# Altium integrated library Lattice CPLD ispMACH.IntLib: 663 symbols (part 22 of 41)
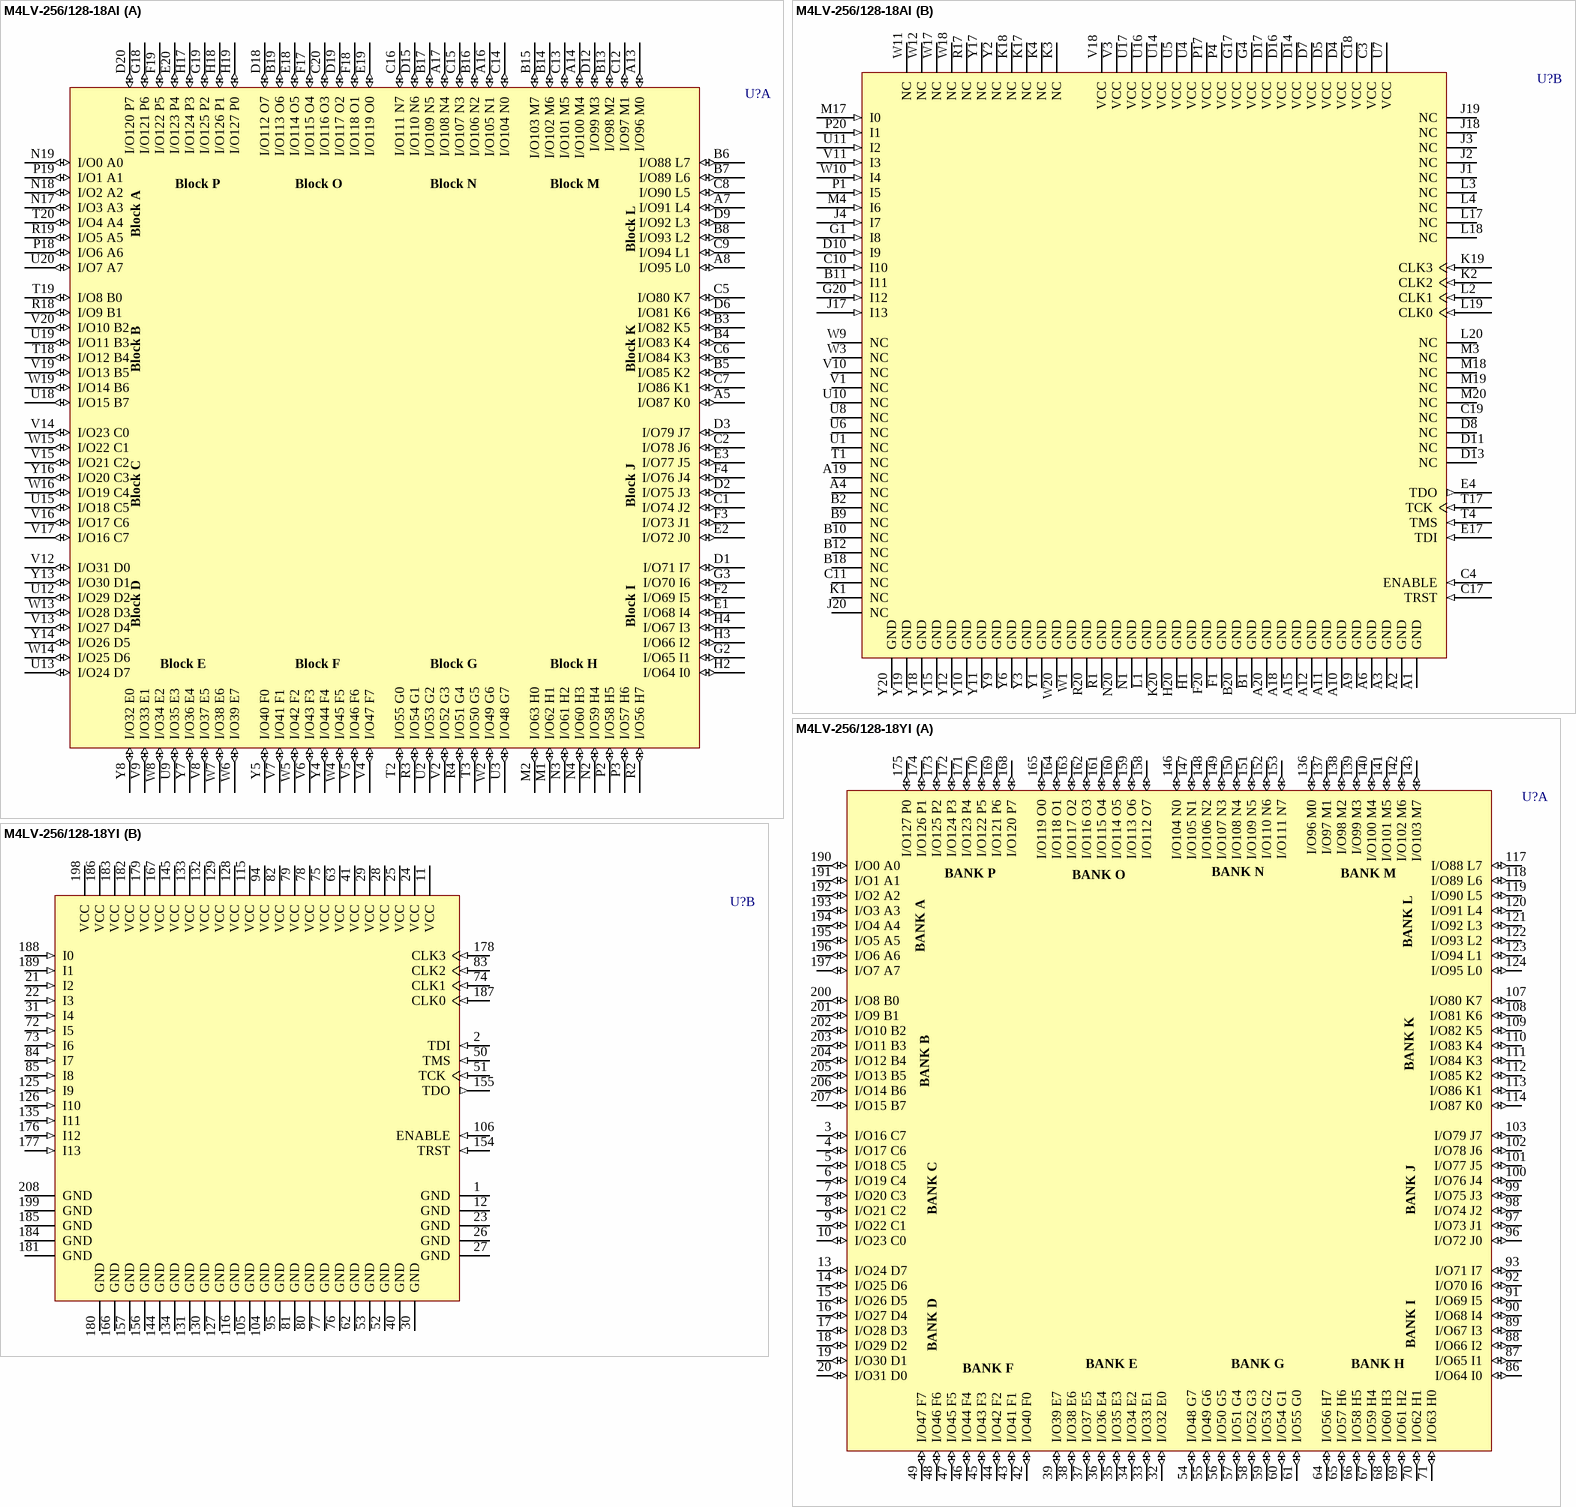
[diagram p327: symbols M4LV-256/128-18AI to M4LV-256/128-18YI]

## M4LV-256/128-18AI
designator U?
High-Performance EE CMOS In-System Programmable Logic
footprint SBGA256 (BGA, 256-Leads, Body 27x27mm, Pitch 1.27mm)
3D model M4LV-SBGA256 (256-Ball Super Ball Grid Array (SBGA256))
part A pins: A5 I/O87 K0 (io), A7 I/O91 L4 (io), A8 I/O95 L0 (io), A13 I/O96 M0 (io), A14 I/O100 M4 (io), A16 I/O105 N1 (io), A17 I/O108 N4 (io), B3 I/O82 K5 (io), B4 I/O83 K4 (io), B5 I/O85 K2 (io), B6 I/O88 L7 (io), B7 I/O89 L6 (io), B8 I/O93 L2 (io), B13 I/O98 M2 (io), B14 I/O102 M6 (io), B15 I/O103 M7 (io), B16 I/O106 N2 (io), B17 I/O109 N5 (io), B19 I/O113 O6 (io), C1 I/O74 J2 (io), C2 I/O78 J6 (io), C5 I/O80 K7 (io), C6 I/O84 K3 (io), C7 I/O86 K1 (io), C8 I/O90 L5 (io), C9 I/O94 L1 (io), C12 I/O97 M1 (io), C13 I/O101 M5 (io), C14 I/O104 N0 (io), C15 I/O107 N3 (io), C16 I/O111 N7 (io), C20 I/O116 O3 (io), D1 I/O71 I7 (io), D2 I/O75 J3 (io), D3 I/O79 J7 (io), D6 I/O81 K6 (io), D9 I/O92 L3 (io), D12 I/O99 M3 (io), D15 I/O110 N6 (io), D18 I/O112 O7 (io), D19 I/O117 O2 (io), D20 I/O120 P7 (io), E1 I/O68 I4 (io), E2 I/O72 J0 (io), E3 I/O77 J5 (io), E18 I/O114 O5 (io), E19 I/O119 O0 (io), E20 I/O123 P4 (io), F2 I/O69 I5 (io), F3 I/O73 J1 (io), F4 I/O76 J4 (io), F17 I/O115 O4 (io), F18 I/O118 O1 (io), F19 I/O122 P5 (io), G2 I/O65 I1 (io), G3 I/O70 I6 (io), G18 I/O121 P6 (io), G19 I/O125 P2 (io), H2 I/O64 I0 (io), H3 I/O66 I2 (io), H4 I/O67 I3 (io), H17 I/O124 P3 (io), H18 I/O126 P1 (io), H19 I/O127 P0 (io), M1 I/O62 H1 (io), M2 I/O63 H0 (io), N2 I/O59 H4 (io), N3 I/O61 H2 (io), N4 I/O60 H3 (io), N17 I/O3 A3 (io), N18 I/O2 A2 (io), N19 I/O0 A0 (io), P2 I/O58 H5 (io), P3 I/O57 H6 (io), P18 I/O6 A6 (io), P19 I/O1 A1 (io), R2 I/O56 H7 (io), R3 I/O54 G1 (io), R4 I/O51 G4 (io), R18 I/O9 B1 (io), R19 I/O5 A5 (io), T2 I/O55 G0 (io), T3 I/O50 G5 (io), T18 I/O12 B4 (io), T19 I/O8 B0 (io), T20 I/O4 A4 (io), U2 I/O53 G2 (io), U3 I/O48 G7 (io), U9 I/O35 E3 (io), U12 I/O29 D2 (io), U13 I/O24 D7 (io), U15 I/O18 C5 (io), U18 I/O15 B7 (io), U19 I/O11 B3 (io), U20 I/O7 A7 (io), V2 I/O52 G3 (io), V4 I/O47 F7 (io), V5 I/O46 F6 (io), V6 I/O43 F3 (io), V7 I/O41 F1 (io), V8 I/O37 E5 (io), V9 I/O33 E1 (io), V12 I/O31 D0 (io), V13 I/O27 D4 (io), V14 I/O23 C0 (io), V15 I/O21 C2 (io), V16 I/O17 C6 (io), V17 I/O16 C7 (io), V19 I/O13 B5 (io), V20 I/O10 B2 (io), W2 I/O49 G6 (io), W4 I/O45 F5 (io), W5 I/O42 F2 (io), W6 I/O39 E7 (io), W7 I/O38 E6 (io), W8 I/O34 E2 (io), W13 I/O28 D3 (io), W14 I/O25 D6 (io), W15 I/O22 C1 (io), W16 I/O19 C4 (io), W19 I/O14 B6 (io), Y4 I/O44 F4 (io), Y5 I/O40 F0 (io), Y7 I/O36 E4 (io), Y8 I/O32 E0 (io), Y13 I/O30 D1 (io), Y14 I/O26 D5 (io), Y16 I/O20 C3 (io)
part B pins: A1 GND (power), A2 GND (power), A3 GND (power), A4 NC, A6 GND (power), A9 GND (power), A10 GND (power), A11 GND (power), A12 GND (power), A15 GND (power), A18 GND (power), A19 NC, A20 GND (power), B1 GND (power), B2 NC, B9 NC, B10 NC, B11 I11 (in), B12 NC, B18 NC, B20 GND (power), C3 VCC (power), C4 ENABLE (in), C10 I10 (in), C11 NC, C17 TRST (in), C18 VCC (power), C19 NC, D4 VCC (power), D5 VCC (power), D7 VCC (power), D8 NC, D10 I9 (in), D11 NC, D13 NC, D14 VCC (power), D16 VCC (power), D17 VCC (power), E4 TDO (out), E17 TDI (in), F1 GND (power), F20 GND (power), G1 I8 (in), G4 VCC (power), G17 VCC (power), G20 I12 (in), H1 GND (power), H20 GND (power), J1 NC, J2 NC, J3 NC, J4 I7 (in), J17 I13 (in), J18 NC, J19 NC, J20 NC, K1 NC, K2 CLK2 (in), K3 NC, K4 NC, K17 NC, K18 NC, K19 CLK3 (in), K20 GND (power), L1 GND (power), L2 CLK1 (in), L3 NC, L4 NC, L17 NC, L18 NC, L19 CLK0 (in), L20 NC, M3 NC, M4 I6 (in), M17 I0 (in), M18 NC, M19 NC, M20 NC, N1 GND (power), N20 GND (power), P1 I5 (in), P4 VCC (power), P17 VCC (power), P20 I1 (in), R1 GND (power), R17 NC, R20 GND (power), T1 NC, T4 TMS (in), T17 TCK (in), U1 NC, U4 VCC (power), U5 VCC (power), U6 NC, U7 VCC (power), U8 NC, U10 NC, U11 I2 (in), U14 VCC (power), U16 VCC (power), U17 VCC (power), V1 NC, V3 VCC (power), V10 NC, V11 I3 (in), V18 VCC (power), W1 GND (power), W3 NC, W9 NC, W10 I4 (in), W11 NC, W12 NC, W17 NC, W18 NC, W20 GND (power), Y1 GND (power), Y2 NC, Y3 GND (power), Y6 GND (power), Y9 GND (power), Y10 GND (power), Y11 GND (power), Y12 GND (power), Y15 GND (power), Y17 NC, Y18 GND (power), Y19 GND (power), Y20 GND (power)

## M4LV-256/128-18YI
designator U?
High-Performance EE CMOS In-System Programmable Logic
footprint PQFP208_N (Shrink QFP, 208-Leads, Body 28x28mm, Pitch 0.5mm, IPC Medium Density)
footprint PQFP208_L (Shrink QFP, 208-Leads, Body 28x28mm, Pitch 0.5mm, IPC High Density)
footprint PQFP208_M (Shrink QFP, 208-Leads, Body 28x28mm, Pitch 0.5mm, IPC Low Density)
3D model M4LV-PQFP208 (208-Pin Plastic Quad Flat Pack (PQFP208))
part A pins: 3 I/O16 C7 (io), 4 I/O17 C6 (io), 5 I/O18 C5 (io), 6 I/O19 C4 (io), 7 I/O20 C3 (io), 8 I/O21 C2 (io), 9 I/O22 C1 (io), 10 I/O23 C0 (io), 13 I/O24 D7 (io), 14 I/O25 D6 (io), 15 I/O26 D5 (io), 16 I/O27 D4 (io), 17 I/O28 D3 (io), 18 I/O29 D2 (io), 19 I/O30 D1 (io), 20 I/O31 D0 (io), 32 I/O32 E0 (io), 33 I/O33 E1 (io), 34 I/O34 E2 (io), 35 I/O35 E3 (io), 36 I/O36 E4 (io), 37 I/O37 E5 (io), 38 I/O38 E6 (io), 39 I/O39 E7 (io), 42 I/O40 F0 (io), 43 I/O41 F1 (io), 44 I/O42 F2 (io), 45 I/O43 F3 (io), 46 I/O44 F4 (io), 47 I/O45 F5 (io), 48 I/O46 F6 (io), 49 I/O47 F7 (io), 54 I/O48 G7 (io), 55 I/O49 G6 (io), 56 I/O50 G5 (io), 57 I/O51 G4 (io), 58 I/O52 G3 (io), 59 I/O53 G2 (io), 60 I/O54 G1 (io), 61 I/O55 G0 (io), 64 I/O56 H7 (io), 65 I/O57 H6 (io), 66 I/O58 H5 (io), 67 I/O59 H4 (io), 68 I/O60 H3 (io), 69 I/O61 H2 (io), 70 I/O62 H1 (io), 71 I/O63 H0 (io), 86 I/O64 I0 (io), 87 I/O65 I1 (io), 88 I/O66 I2 (io), 89 I/O67 I3 (io), 90 I/O68 I4 (io), 91 I/O69 I5 (io), 92 I/O70 I6 (io), 93 I/O71 I7 (io), 96 I/O72 J0 (io), 97 I/O73 J1 (io), 98 I/O74 J2 (io), 99 I/O75 J3 (io), 100 I/O76 J4 (io), 101 I/O77 J5 (io), 102 I/O78 J6 (io), 103 I/O79 J7 (io), 107 I/O80 K7 (io), 108 I/O81 K6 (io), 109 I/O82 K5 (io), 110 I/O83 K4 (io), 111 I/O84 K3 (io), 112 I/O85 K2 (io), 113 I/O86 K1 (io), 114 I/O87 K0 (io), 117 I/O88 L7 (io), 118 I/O89 L6 (io), 119 I/O90 L5 (io), 120 I/O91 L4 (io), 121 I/O92 L3 (io), 122 I/O93 L2 (io), 123 I/O94 L1 (io), 124 I/O95 L0 (io), 136 I/O96 M0 (io), 137 I/O97 M1 (io), 138 I/O98 M2 (io), 139 I/O99 M3 (io), 140 I/O100 M4 (io), 141 I/O101 M5 (io), 142 I/O102 M6 (io), 143 I/O103 M7 (io), 146 I/O104 N0 (io), 147 I/O105 N1 (io), 148 I/O106 N2 (io), 149 I/O107 N3 (io), 150 I/O108 N4 (io), 151 I/O109 N5 (io), 152 I/O110 N6 (io), 153 I/O111 N7 (io), 158 I/O112 O7 (io), 159 I/O113 O6 (io), 160 I/O114 O5 (io), 161 I/O115 O4 (io), 162 I/O116 O3 (io), 163 I/O117 O2 (io), 164 I/O118 O1 (io), 165 I/O119 O0 (io), 168 I/O120 P7 (io), 169 I/O121 P6 (io), 170 I/O122 P5 (io), 171 I/O123 P4 (io), 172 I/O124 P3 (io), 173 I/O125 P2 (io), 174 I/O126 P1 (io), 175 I/O127 P0 (io), 190 I/O0 A0 (io), 191 I/O1 A1 (io), 192 I/O2 A2 (io), 193 I/O3 A3 (io), 194 I/O4 A4 (io), 195 I/O5 A5 (io), 196 I/O6 A6 (io), 197 I/O7 A7 (io), 200 I/O8 B0 (io), 201 I/O9 B1 (io), 202 I/O10 B2 (io), 203 I/O11 B3 (io), 204 I/O12 B4 (io), 205 I/O13 B5 (io), 206 I/O14 B6 (io), 207 I/O15 B7 (io)
part B pins: 1 GND (power), 2 TDI (in), 11 VCC (power), 12 GND (power), 21 I2 (in), 22 I3 (in), 23 GND (power), 24 VCC (power), 25 VCC (power), 26 GND (power), 27 GND (power), 28 VCC (power), 29 VCC (power), 30 GND (power), 31 I4 (in), 40 GND (power), 41 VCC (power), 50 TMS (in), 51 TCK (in), 52 GND (power), 53 GND (power), 62 GND (power), 63 VCC (power), 72 I5 (in), 73 I6 (in), 74 CLK1 (in), 75 VCC (power), 76 GND (power), 77 GND (power), 78 VCC (power), 79 VCC (power), 80 GND (power), 81 GND (power), 82 VCC (power), 83 CLK2 (in), 84 I7 (in), 85 I8 (in), 94 VCC (power), 95 GND (power), 104 GND (power), 105 GND (power), 106 ENABLE (in), 115 VCC (power), 116 GND (power), 125 I9 (in), 126 I10 (in), 127 GND (power), 128 VCC (power), 129 VCC (power), 130 GND (power), 131 GND (power), 132 VCC (power), 133 VCC (power), 134 GND (power), 135 I11 (in), 144 GND (power), 145 VCC (power), 154 TRST (in), 155 TDO (out), 156 GND (power), 157 GND (power), 166 GND (power), 167 VCC (power), 176 I12 (in), 177 I13 (in), 178 CLK3 (in), 179 VCC (power), 180 GND (power), 181 GND (power), 182 VCC (power), 183 VCC (power), 184 GND (power), 185 GND (power), 186 VCC (power), 187 CLK0 (in), 188 I0 (in), 189 I1 (in), 198 VCC (power), 199 GND (power), 208 GND (power)

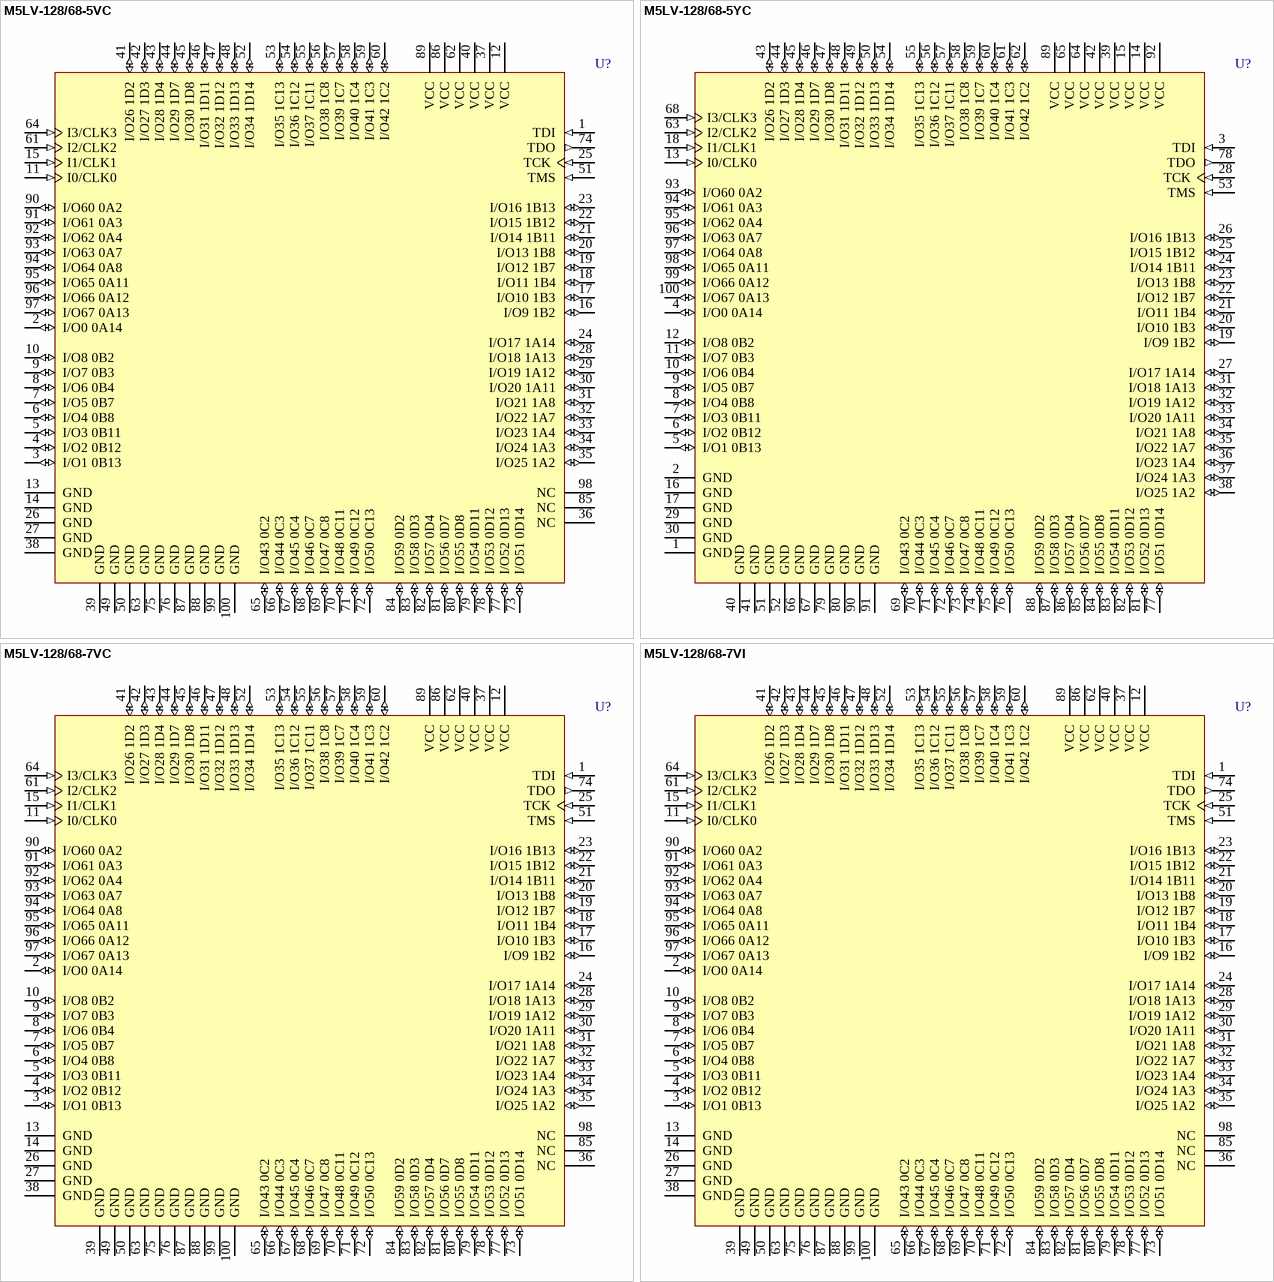
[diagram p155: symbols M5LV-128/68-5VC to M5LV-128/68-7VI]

## M5LV-128/68-5VC
designator U?
High-Density and High-I/O Complex PLD
footprint TQFP100_N (Thin QFP, 100-Leads, Body 14x14mm, Pitch 0.5mm, IPC Medium Density)
footprint TQFP100_L (Thin QFP, 100-Leads, Body 14x14mm, Pitch 0.5mm, IPC High Density)
footprint TQFP100_M (Thin QFP, 100-Leads, Body 14x14mm, Pitch 0.5mm, IPC Low Density)
3D model M5LV-TQFP100 (100-Pin Thin Quad Flat Pack (TQFP100))
pins: 1 TDI (in), 2 I/O0 0A14 (io), 3 I/O1 0B13 (io), 4 I/O2 0B12 (io), 5 I/O3 0B11 (io), 6 I/O4 0B8 (io), 7 I/O5 0B7 (io), 8 I/O6 0B4 (io), 9 I/O7 0B3 (io), 10 I/O8 0B2 (io), 11 I0/CLK0 (in), 12 VCC (power), 13 GND (power), 14 GND (power), 15 I1/CLK1 (in), 16 I/O9 1B2 (io), 17 I/O10 1B3 (io), 18 I/O11 1B4 (io), 19 I/O12 1B7 (io), 20 I/O13 1B8 (io), 21 I/O14 1B11 (io), 22 I/O15 1B12 (io), 23 I/O16 1B13 (io), 24 I/O17 1A14 (io), 25 TCK (in), 26 GND (power), 27 GND (power), 28 I/O18 1A13 (io), 29 I/O19 1A12 (io), 30 I/O20 1A11 (io), 31 I/O21 1A8 (io), 32 I/O22 1A7 (io), 33 I/O23 1A4 (io), 34 I/O24 1A3 (io), 35 I/O25 1A2 (io), 36 NC, 37 VCC (power), 38 GND (power), 39 GND (power), 40 VCC (power), 41 I/O26 1D2 (io), 42 I/O27 1D3 (io), 43 I/O28 1D4 (io), 44 I/O29 1D7 (io), 45 I/O30 1D8 (io), 46 I/O31 1D11 (io), 47 I/O32 1D12 (io), 48 I/O33 1D13 (io), 49 GND (power), 50 GND (power), 51 TMS (in), 52 I/O34 1D14 (io), 53 I/O35 1C13 (io), 54 I/O36 1C12 (io), 55 I/O37 1C11 (io), 56 I/O38 1C8 (io), 57 I/O39 1C7 (io), 58 I/O40 1C4 (io), 59 I/O41 1C3 (io), 60 I/O42 1C2 (io), 61 I2/CLK2 (in), 62 VCC (power), 63 GND (power), 64 I3/CLK3 (in), 65 I/O43 0C2 (io), 66 I/O44 0C3 (io), 67 I/O45 0C4 (io), 68 I/O46 0C7 (io), 69 I/O47 0C8 (io), 70 I/O48 0C11 (io), 71 I/O49 0C12 (io), 72 I/O50 0C13 (io), 73 I/O51 0D14 (io), 74 TDO (out), 75 GND (power), 76 GND (power), 77 I/O52 0D13 (io), 78 I/O53 0D12 (io), 79 I/O54 0D11 (io), 80 I/O55 0D8 (io), 81 I/O56 0D7 (io), 82 I/O57 0D4 (io), 83 I/O58 0D3 (io), 84 I/O59 0D2 (io), 85 NC, 86 VCC (power), 87 GND (power), 88 GND (power), 89 VCC (power), 90 I/O60 0A2 (io), 91 I/O61 0A3 (io), 92 I/O62 0A4 (io), 93 I/O63 0A7 (io), 94 I/O64 0A8 (io), 95 I/O65 0A11 (io), 96 I/O66 0A12 (io), 97 I/O67 0A13 (io), 98 NC, 99 GND (power), 100 GND (power)

## M5LV-128/68-5YC
designator U?
High-Density and High-I/O Complex PLD
footprint PQFP100_N (QFP, 100-Leads, Body 20x14mm, Pitch 0.65mm, IPC Medium Density)
footprint PQFP100_L (QFP, 100-Leads, Body 20x14mm, Pitch 0.65mm, IPC High Density)
footprint PQFP100_M (QFP, 100-Leads, Body 20x14mm, Pitch 0.65mm, IPC Low Density)
3D model PQFP-100 (100-Pin Quad Flat Pack Rectangular 0.65 mm Pitch)
pins: 1 GND (power), 2 GND (power), 3 TDI (in), 4 I/O0 0A14 (io), 5 I/O1 0B13 (io), 6 I/O2 0B12 (io), 7 I/O3 0B11 (io), 8 I/O4 0B8 (io), 9 I/O5 0B7 (io), 10 I/O6 0B4 (io), 11 I/O7 0B3 (io), 12 I/O8 0B2 (io), 13 I0/CLK0 (in), 14 VCC (power), 15 VCC (power), 16 GND (power), 17 GND (power), 18 I1/CLK1 (in), 19 I/O9 1B2 (io), 20 I/O10 1B3 (io), 21 I/O11 1B4 (io), 22 I/O12 1B7 (io), 23 I/O13 1B8 (io), 24 I/O14 1B11 (io), 25 I/O15 1B12 (io), 26 I/O16 1B13 (io), 27 I/O17 1A14 (io), 28 TCK (in), 29 GND (power), 30 GND (power), 31 I/O18 1A13 (io), 32 I/O19 1A12 (io), 33 I/O20 1A11 (io), 34 I/O21 1A8 (io), 35 I/O22 1A7 (io), 36 I/O23 1A4 (io), 37 I/O24 1A3 (io), 38 I/O25 1A2 (io), 39 VCC (power), 40 GND (power), 41 GND (power), 42 VCC (power), 43 I/O26 1D2 (io), 44 I/O27 1D3 (io), 45 I/O28 1D4 (io), 46 I/O29 1D7 (io), 47 I/O30 1D8 (io), 48 I/O31 1D11 (io), 49 I/O32 1D12 (io), 50 I/O33 1D13 (io), 51 GND (power), 52 GND (power), 53 TMS (in), 54 I/O34 1D14 (io), 55 I/O35 1C13 (io), 56 I/O36 1C12 (io), 57 I/O37 1C11 (io), 58 I/O38 1C8 (io), 59 I/O39 1C7 (io), 60 I/O40 1C4 (io), 61 I/O41 1C3 (io), 62 I/O42 1C2 (io), 63 I2/CLK2 (in), 64 VCC (power), 65 VCC (power), 66 GND (power), 67 GND (power), 68 I3/CLK3 (in), 69 I/O43 0C2 (io), 70 I/O44 0C3 (io), 71 I/O45 0C4 (io), 72 I/O46 0C7 (io), 73 I/O47 0C8 (io), 74 I/O48 0C11 (io), 75 I/O49 0C12 (io), 76 I/O50 0C13 (io), 77 I/O51 0D14 (io), 78 TDO (out), 79 GND (power), 80 GND (power), 81 I/O52 0D13 (io), 82 I/O53 0D12 (io), 83 I/O54 0D11 (io), 84 I/O55 0D8 (io), 85 I/O56 0D7 (io), 86 I/O57 0D4 (io), 87 I/O58 0D3 (io), 88 I/O59 0D2 (io), 89 VCC (power), 90 GND (power), 91 GND (power), 92 VCC (power), 93 I/O60 0A2 (io), 94 I/O61 0A3 (io), 95 I/O62 0A4 (io), 96 I/O63 0A7 (io), 97 I/O64 0A8 (io), 98 I/O65 0A11 (io), 99 I/O66 0A12 (io), 100 I/O67 0A13 (io)

## M5LV-128/68-7VC
designator U?
High-Density and High-I/O Complex PLD
footprint TQFP100_N (Thin QFP, 100-Leads, Body 14x14mm, Pitch 0.5mm, IPC Medium Density)
footprint TQFP100_L (Thin QFP, 100-Leads, Body 14x14mm, Pitch 0.5mm, IPC High Density)
footprint TQFP100_M (Thin QFP, 100-Leads, Body 14x14mm, Pitch 0.5mm, IPC Low Density)
3D model M5LV-TQFP100 (100-Pin Thin Quad Flat Pack (TQFP100))
pins: 1 TDI (in), 2 I/O0 0A14 (io), 3 I/O1 0B13 (io), 4 I/O2 0B12 (io), 5 I/O3 0B11 (io), 6 I/O4 0B8 (io), 7 I/O5 0B7 (io), 8 I/O6 0B4 (io), 9 I/O7 0B3 (io), 10 I/O8 0B2 (io), 11 I0/CLK0 (in), 12 VCC (power), 13 GND (power), 14 GND (power), 15 I1/CLK1 (in), 16 I/O9 1B2 (io), 17 I/O10 1B3 (io), 18 I/O11 1B4 (io), 19 I/O12 1B7 (io), 20 I/O13 1B8 (io), 21 I/O14 1B11 (io), 22 I/O15 1B12 (io), 23 I/O16 1B13 (io), 24 I/O17 1A14 (io), 25 TCK (in), 26 GND (power), 27 GND (power), 28 I/O18 1A13 (io), 29 I/O19 1A12 (io), 30 I/O20 1A11 (io), 31 I/O21 1A8 (io), 32 I/O22 1A7 (io), 33 I/O23 1A4 (io), 34 I/O24 1A3 (io), 35 I/O25 1A2 (io), 36 NC, 37 VCC (power), 38 GND (power), 39 GND (power), 40 VCC (power), 41 I/O26 1D2 (io), 42 I/O27 1D3 (io), 43 I/O28 1D4 (io), 44 I/O29 1D7 (io), 45 I/O30 1D8 (io), 46 I/O31 1D11 (io), 47 I/O32 1D12 (io), 48 I/O33 1D13 (io), 49 GND (power), 50 GND (power), 51 TMS (in), 52 I/O34 1D14 (io), 53 I/O35 1C13 (io), 54 I/O36 1C12 (io), 55 I/O37 1C11 (io), 56 I/O38 1C8 (io), 57 I/O39 1C7 (io), 58 I/O40 1C4 (io), 59 I/O41 1C3 (io), 60 I/O42 1C2 (io), 61 I2/CLK2 (in), 62 VCC (power), 63 GND (power), 64 I3/CLK3 (in), 65 I/O43 0C2 (io), 66 I/O44 0C3 (io), 67 I/O45 0C4 (io), 68 I/O46 0C7 (io), 69 I/O47 0C8 (io), 70 I/O48 0C11 (io), 71 I/O49 0C12 (io), 72 I/O50 0C13 (io), 73 I/O51 0D14 (io), 74 TDO (out), 75 GND (power), 76 GND (power), 77 I/O52 0D13 (io), 78 I/O53 0D12 (io), 79 I/O54 0D11 (io), 80 I/O55 0D8 (io), 81 I/O56 0D7 (io), 82 I/O57 0D4 (io), 83 I/O58 0D3 (io), 84 I/O59 0D2 (io), 85 NC, 86 VCC (power), 87 GND (power), 88 GND (power), 89 VCC (power), 90 I/O60 0A2 (io), 91 I/O61 0A3 (io), 92 I/O62 0A4 (io), 93 I/O63 0A7 (io), 94 I/O64 0A8 (io), 95 I/O65 0A11 (io), 96 I/O66 0A12 (io), 97 I/O67 0A13 (io), 98 NC, 99 GND (power), 100 GND (power)

## M5LV-128/68-7VI
designator U?
High-Density and High-I/O Complex PLD
footprint TQFP100_N (Thin QFP, 100-Leads, Body 14x14mm, Pitch 0.5mm, IPC Medium Density)
footprint TQFP100_L (Thin QFP, 100-Leads, Body 14x14mm, Pitch 0.5mm, IPC High Density)
footprint TQFP100_M (Thin QFP, 100-Leads, Body 14x14mm, Pitch 0.5mm, IPC Low Density)
3D model M5LV-TQFP100 (100-Pin Thin Quad Flat Pack (TQFP100))
pins: 1 TDI (in), 2 I/O0 0A14 (io), 3 I/O1 0B13 (io), 4 I/O2 0B12 (io), 5 I/O3 0B11 (io), 6 I/O4 0B8 (io), 7 I/O5 0B7 (io), 8 I/O6 0B4 (io), 9 I/O7 0B3 (io), 10 I/O8 0B2 (io), 11 I0/CLK0 (in), 12 VCC (power), 13 GND (power), 14 GND (power), 15 I1/CLK1 (in), 16 I/O9 1B2 (io), 17 I/O10 1B3 (io), 18 I/O11 1B4 (io), 19 I/O12 1B7 (io), 20 I/O13 1B8 (io), 21 I/O14 1B11 (io), 22 I/O15 1B12 (io), 23 I/O16 1B13 (io), 24 I/O17 1A14 (io), 25 TCK (in), 26 GND (power), 27 GND (power), 28 I/O18 1A13 (io), 29 I/O19 1A12 (io), 30 I/O20 1A11 (io), 31 I/O21 1A8 (io), 32 I/O22 1A7 (io), 33 I/O23 1A4 (io), 34 I/O24 1A3 (io), 35 I/O25 1A2 (io), 36 NC, 37 VCC (power), 38 GND (power), 39 GND (power), 40 VCC (power), 41 I/O26 1D2 (io), 42 I/O27 1D3 (io), 43 I/O28 1D4 (io), 44 I/O29 1D7 (io), 45 I/O30 1D8 (io), 46 I/O31 1D11 (io), 47 I/O32 1D12 (io), 48 I/O33 1D13 (io), 49 GND (power), 50 GND (power), 51 TMS (in), 52 I/O34 1D14 (io), 53 I/O35 1C13 (io), 54 I/O36 1C12 (io), 55 I/O37 1C11 (io), 56 I/O38 1C8 (io), 57 I/O39 1C7 (io), 58 I/O40 1C4 (io), 59 I/O41 1C3 (io), 60 I/O42 1C2 (io), 61 I2/CLK2 (in), 62 VCC (power), 63 GND (power), 64 I3/CLK3 (in), 65 I/O43 0C2 (io), 66 I/O44 0C3 (io), 67 I/O45 0C4 (io), 68 I/O46 0C7 (io), 69 I/O47 0C8 (io), 70 I/O48 0C11 (io), 71 I/O49 0C12 (io), 72 I/O50 0C13 (io), 73 I/O51 0D14 (io), 74 TDO (out), 75 GND (power), 76 GND (power), 77 I/O52 0D13 (io), 78 I/O53 0D12 (io), 79 I/O54 0D11 (io), 80 I/O55 0D8 (io), 81 I/O56 0D7 (io), 82 I/O57 0D4 (io), 83 I/O58 0D3 (io), 84 I/O59 0D2 (io), 85 NC, 86 VCC (power), 87 GND (power), 88 GND (power), 89 VCC (power), 90 I/O60 0A2 (io), 91 I/O61 0A3 (io), 92 I/O62 0A4 (io), 93 I/O63 0A7 (io), 94 I/O64 0A8 (io), 95 I/O65 0A11 (io), 96 I/O66 0A12 (io), 97 I/O67 0A13 (io), 98 NC, 99 GND (power), 100 GND (power)

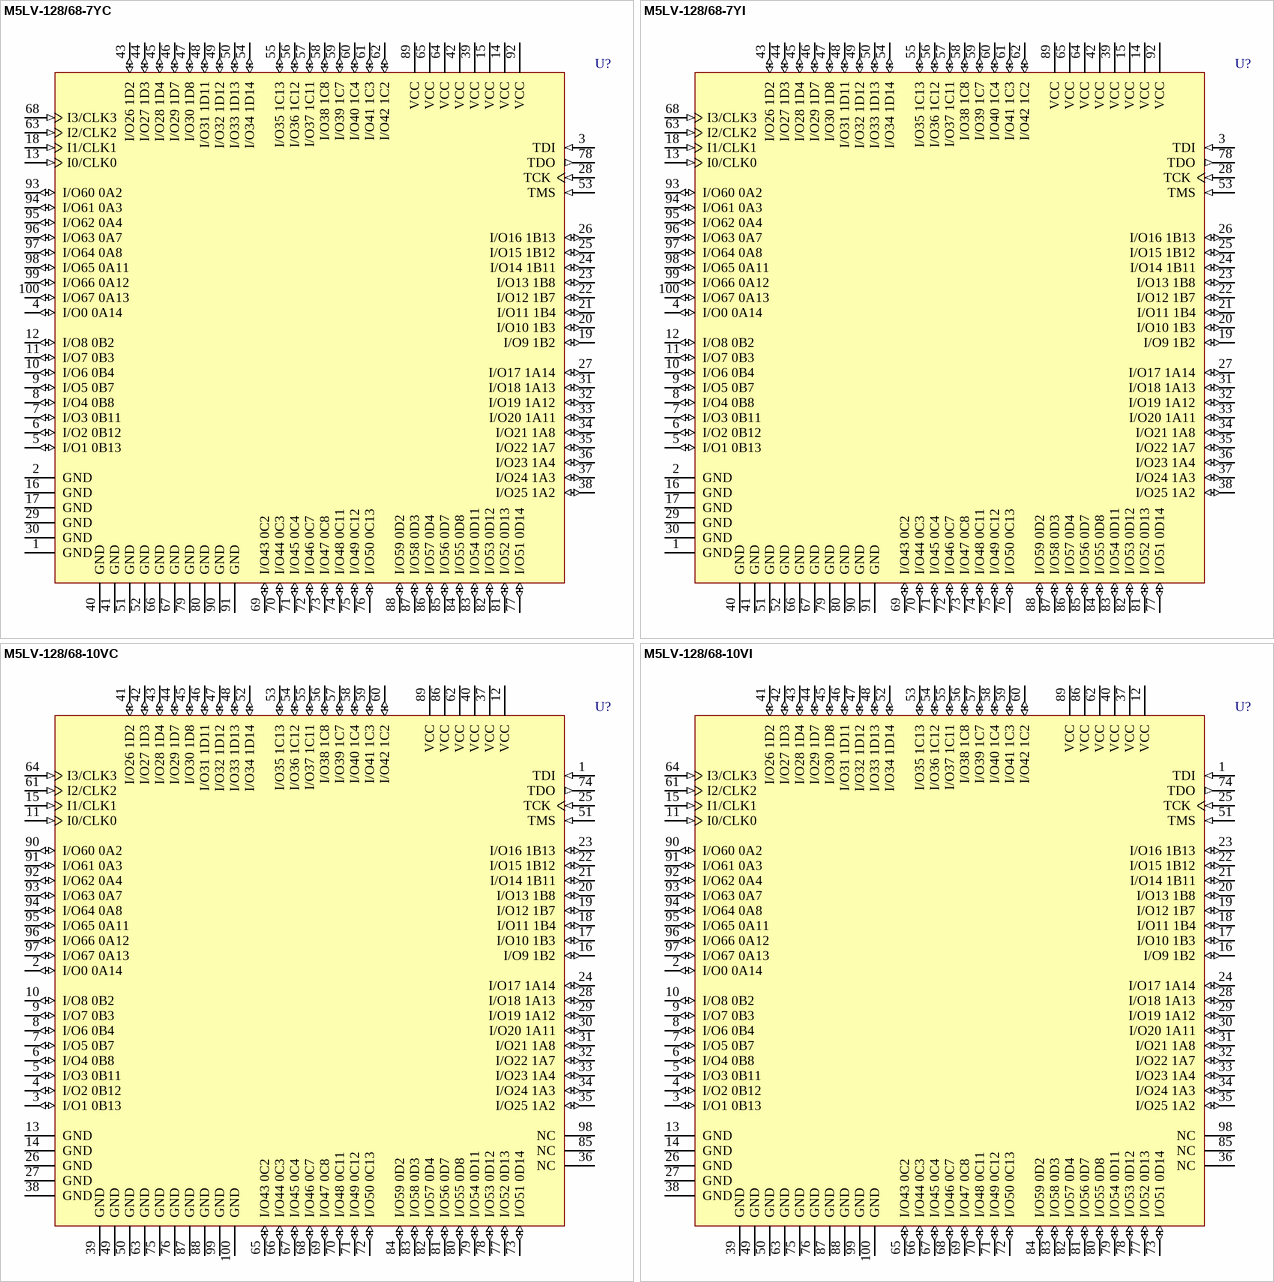
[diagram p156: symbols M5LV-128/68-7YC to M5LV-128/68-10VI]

## M5LV-128/68-7YC
designator U?
High-Density and High-I/O Complex PLD
footprint PQFP100_N (QFP, 100-Leads, Body 20x14mm, Pitch 0.65mm, IPC Medium Density)
footprint PQFP100_L (QFP, 100-Leads, Body 20x14mm, Pitch 0.65mm, IPC High Density)
footprint PQFP100_M (QFP, 100-Leads, Body 20x14mm, Pitch 0.65mm, IPC Low Density)
3D model PQFP-100 (100-Pin Quad Flat Pack Rectangular 0.65 mm Pitch)
pins: 1 GND (power), 2 GND (power), 3 TDI (in), 4 I/O0 0A14 (io), 5 I/O1 0B13 (io), 6 I/O2 0B12 (io), 7 I/O3 0B11 (io), 8 I/O4 0B8 (io), 9 I/O5 0B7 (io), 10 I/O6 0B4 (io), 11 I/O7 0B3 (io), 12 I/O8 0B2 (io), 13 I0/CLK0 (in), 14 VCC (power), 15 VCC (power), 16 GND (power), 17 GND (power), 18 I1/CLK1 (in), 19 I/O9 1B2 (io), 20 I/O10 1B3 (io), 21 I/O11 1B4 (io), 22 I/O12 1B7 (io), 23 I/O13 1B8 (io), 24 I/O14 1B11 (io), 25 I/O15 1B12 (io), 26 I/O16 1B13 (io), 27 I/O17 1A14 (io), 28 TCK (in), 29 GND (power), 30 GND (power), 31 I/O18 1A13 (io), 32 I/O19 1A12 (io), 33 I/O20 1A11 (io), 34 I/O21 1A8 (io), 35 I/O22 1A7 (io), 36 I/O23 1A4 (io), 37 I/O24 1A3 (io), 38 I/O25 1A2 (io), 39 VCC (power), 40 GND (power), 41 GND (power), 42 VCC (power), 43 I/O26 1D2 (io), 44 I/O27 1D3 (io), 45 I/O28 1D4 (io), 46 I/O29 1D7 (io), 47 I/O30 1D8 (io), 48 I/O31 1D11 (io), 49 I/O32 1D12 (io), 50 I/O33 1D13 (io), 51 GND (power), 52 GND (power), 53 TMS (in), 54 I/O34 1D14 (io), 55 I/O35 1C13 (io), 56 I/O36 1C12 (io), 57 I/O37 1C11 (io), 58 I/O38 1C8 (io), 59 I/O39 1C7 (io), 60 I/O40 1C4 (io), 61 I/O41 1C3 (io), 62 I/O42 1C2 (io), 63 I2/CLK2 (in), 64 VCC (power), 65 VCC (power), 66 GND (power), 67 GND (power), 68 I3/CLK3 (in), 69 I/O43 0C2 (io), 70 I/O44 0C3 (io), 71 I/O45 0C4 (io), 72 I/O46 0C7 (io), 73 I/O47 0C8 (io), 74 I/O48 0C11 (io), 75 I/O49 0C12 (io), 76 I/O50 0C13 (io), 77 I/O51 0D14 (io), 78 TDO (out), 79 GND (power), 80 GND (power), 81 I/O52 0D13 (io), 82 I/O53 0D12 (io), 83 I/O54 0D11 (io), 84 I/O55 0D8 (io), 85 I/O56 0D7 (io), 86 I/O57 0D4 (io), 87 I/O58 0D3 (io), 88 I/O59 0D2 (io), 89 VCC (power), 90 GND (power), 91 GND (power), 92 VCC (power), 93 I/O60 0A2 (io), 94 I/O61 0A3 (io), 95 I/O62 0A4 (io), 96 I/O63 0A7 (io), 97 I/O64 0A8 (io), 98 I/O65 0A11 (io), 99 I/O66 0A12 (io), 100 I/O67 0A13 (io)

## M5LV-128/68-7YI
designator U?
High-Density and High-I/O Complex PLD
footprint PQFP100_N (QFP, 100-Leads, Body 20x14mm, Pitch 0.65mm, IPC Medium Density)
footprint PQFP100_L (QFP, 100-Leads, Body 20x14mm, Pitch 0.65mm, IPC High Density)
footprint PQFP100_M (QFP, 100-Leads, Body 20x14mm, Pitch 0.65mm, IPC Low Density)
3D model PQFP-100 (100-Pin Quad Flat Pack Rectangular 0.65 mm Pitch)
pins: 1 GND (power), 2 GND (power), 3 TDI (in), 4 I/O0 0A14 (io), 5 I/O1 0B13 (io), 6 I/O2 0B12 (io), 7 I/O3 0B11 (io), 8 I/O4 0B8 (io), 9 I/O5 0B7 (io), 10 I/O6 0B4 (io), 11 I/O7 0B3 (io), 12 I/O8 0B2 (io), 13 I0/CLK0 (in), 14 VCC (power), 15 VCC (power), 16 GND (power), 17 GND (power), 18 I1/CLK1 (in), 19 I/O9 1B2 (io), 20 I/O10 1B3 (io), 21 I/O11 1B4 (io), 22 I/O12 1B7 (io), 23 I/O13 1B8 (io), 24 I/O14 1B11 (io), 25 I/O15 1B12 (io), 26 I/O16 1B13 (io), 27 I/O17 1A14 (io), 28 TCK (in), 29 GND (power), 30 GND (power), 31 I/O18 1A13 (io), 32 I/O19 1A12 (io), 33 I/O20 1A11 (io), 34 I/O21 1A8 (io), 35 I/O22 1A7 (io), 36 I/O23 1A4 (io), 37 I/O24 1A3 (io), 38 I/O25 1A2 (io), 39 VCC (power), 40 GND (power), 41 GND (power), 42 VCC (power), 43 I/O26 1D2 (io), 44 I/O27 1D3 (io), 45 I/O28 1D4 (io), 46 I/O29 1D7 (io), 47 I/O30 1D8 (io), 48 I/O31 1D11 (io), 49 I/O32 1D12 (io), 50 I/O33 1D13 (io), 51 GND (power), 52 GND (power), 53 TMS (in), 54 I/O34 1D14 (io), 55 I/O35 1C13 (io), 56 I/O36 1C12 (io), 57 I/O37 1C11 (io), 58 I/O38 1C8 (io), 59 I/O39 1C7 (io), 60 I/O40 1C4 (io), 61 I/O41 1C3 (io), 62 I/O42 1C2 (io), 63 I2/CLK2 (in), 64 VCC (power), 65 VCC (power), 66 GND (power), 67 GND (power), 68 I3/CLK3 (in), 69 I/O43 0C2 (io), 70 I/O44 0C3 (io), 71 I/O45 0C4 (io), 72 I/O46 0C7 (io), 73 I/O47 0C8 (io), 74 I/O48 0C11 (io), 75 I/O49 0C12 (io), 76 I/O50 0C13 (io), 77 I/O51 0D14 (io), 78 TDO (out), 79 GND (power), 80 GND (power), 81 I/O52 0D13 (io), 82 I/O53 0D12 (io), 83 I/O54 0D11 (io), 84 I/O55 0D8 (io), 85 I/O56 0D7 (io), 86 I/O57 0D4 (io), 87 I/O58 0D3 (io), 88 I/O59 0D2 (io), 89 VCC (power), 90 GND (power), 91 GND (power), 92 VCC (power), 93 I/O60 0A2 (io), 94 I/O61 0A3 (io), 95 I/O62 0A4 (io), 96 I/O63 0A7 (io), 97 I/O64 0A8 (io), 98 I/O65 0A11 (io), 99 I/O66 0A12 (io), 100 I/O67 0A13 (io)

## M5LV-128/68-10VC
designator U?
High-Density and High-I/O Complex PLD
footprint TQFP100_N (Thin QFP, 100-Leads, Body 14x14mm, Pitch 0.5mm, IPC Medium Density)
footprint TQFP100_L (Thin QFP, 100-Leads, Body 14x14mm, Pitch 0.5mm, IPC High Density)
footprint TQFP100_M (Thin QFP, 100-Leads, Body 14x14mm, Pitch 0.5mm, IPC Low Density)
3D model M5LV-TQFP100 (100-Pin Thin Quad Flat Pack (TQFP100))
pins: 1 TDI (in), 2 I/O0 0A14 (io), 3 I/O1 0B13 (io), 4 I/O2 0B12 (io), 5 I/O3 0B11 (io), 6 I/O4 0B8 (io), 7 I/O5 0B7 (io), 8 I/O6 0B4 (io), 9 I/O7 0B3 (io), 10 I/O8 0B2 (io), 11 I0/CLK0 (in), 12 VCC (power), 13 GND (power), 14 GND (power), 15 I1/CLK1 (in), 16 I/O9 1B2 (io), 17 I/O10 1B3 (io), 18 I/O11 1B4 (io), 19 I/O12 1B7 (io), 20 I/O13 1B8 (io), 21 I/O14 1B11 (io), 22 I/O15 1B12 (io), 23 I/O16 1B13 (io), 24 I/O17 1A14 (io), 25 TCK (in), 26 GND (power), 27 GND (power), 28 I/O18 1A13 (io), 29 I/O19 1A12 (io), 30 I/O20 1A11 (io), 31 I/O21 1A8 (io), 32 I/O22 1A7 (io), 33 I/O23 1A4 (io), 34 I/O24 1A3 (io), 35 I/O25 1A2 (io), 36 NC, 37 VCC (power), 38 GND (power), 39 GND (power), 40 VCC (power), 41 I/O26 1D2 (io), 42 I/O27 1D3 (io), 43 I/O28 1D4 (io), 44 I/O29 1D7 (io), 45 I/O30 1D8 (io), 46 I/O31 1D11 (io), 47 I/O32 1D12 (io), 48 I/O33 1D13 (io), 49 GND (power), 50 GND (power), 51 TMS (in), 52 I/O34 1D14 (io), 53 I/O35 1C13 (io), 54 I/O36 1C12 (io), 55 I/O37 1C11 (io), 56 I/O38 1C8 (io), 57 I/O39 1C7 (io), 58 I/O40 1C4 (io), 59 I/O41 1C3 (io), 60 I/O42 1C2 (io), 61 I2/CLK2 (in), 62 VCC (power), 63 GND (power), 64 I3/CLK3 (in), 65 I/O43 0C2 (io), 66 I/O44 0C3 (io), 67 I/O45 0C4 (io), 68 I/O46 0C7 (io), 69 I/O47 0C8 (io), 70 I/O48 0C11 (io), 71 I/O49 0C12 (io), 72 I/O50 0C13 (io), 73 I/O51 0D14 (io), 74 TDO (out), 75 GND (power), 76 GND (power), 77 I/O52 0D13 (io), 78 I/O53 0D12 (io), 79 I/O54 0D11 (io), 80 I/O55 0D8 (io), 81 I/O56 0D7 (io), 82 I/O57 0D4 (io), 83 I/O58 0D3 (io), 84 I/O59 0D2 (io), 85 NC, 86 VCC (power), 87 GND (power), 88 GND (power), 89 VCC (power), 90 I/O60 0A2 (io), 91 I/O61 0A3 (io), 92 I/O62 0A4 (io), 93 I/O63 0A7 (io), 94 I/O64 0A8 (io), 95 I/O65 0A11 (io), 96 I/O66 0A12 (io), 97 I/O67 0A13 (io), 98 NC, 99 GND (power), 100 GND (power)

## M5LV-128/68-10VI
designator U?
High-Density and High-I/O Complex PLD
footprint TQFP100_N (Thin QFP, 100-Leads, Body 14x14mm, Pitch 0.5mm, IPC Medium Density)
footprint TQFP100_L (Thin QFP, 100-Leads, Body 14x14mm, Pitch 0.5mm, IPC High Density)
footprint TQFP100_M (Thin QFP, 100-Leads, Body 14x14mm, Pitch 0.5mm, IPC Low Density)
3D model M5LV-TQFP100 (100-Pin Thin Quad Flat Pack (TQFP100))
pins: 1 TDI (in), 2 I/O0 0A14 (io), 3 I/O1 0B13 (io), 4 I/O2 0B12 (io), 5 I/O3 0B11 (io), 6 I/O4 0B8 (io), 7 I/O5 0B7 (io), 8 I/O6 0B4 (io), 9 I/O7 0B3 (io), 10 I/O8 0B2 (io), 11 I0/CLK0 (in), 12 VCC (power), 13 GND (power), 14 GND (power), 15 I1/CLK1 (in), 16 I/O9 1B2 (io), 17 I/O10 1B3 (io), 18 I/O11 1B4 (io), 19 I/O12 1B7 (io), 20 I/O13 1B8 (io), 21 I/O14 1B11 (io), 22 I/O15 1B12 (io), 23 I/O16 1B13 (io), 24 I/O17 1A14 (io), 25 TCK (in), 26 GND (power), 27 GND (power), 28 I/O18 1A13 (io), 29 I/O19 1A12 (io), 30 I/O20 1A11 (io), 31 I/O21 1A8 (io), 32 I/O22 1A7 (io), 33 I/O23 1A4 (io), 34 I/O24 1A3 (io), 35 I/O25 1A2 (io), 36 NC, 37 VCC (power), 38 GND (power), 39 GND (power), 40 VCC (power), 41 I/O26 1D2 (io), 42 I/O27 1D3 (io), 43 I/O28 1D4 (io), 44 I/O29 1D7 (io), 45 I/O30 1D8 (io), 46 I/O31 1D11 (io), 47 I/O32 1D12 (io), 48 I/O33 1D13 (io), 49 GND (power), 50 GND (power), 51 TMS (in), 52 I/O34 1D14 (io), 53 I/O35 1C13 (io), 54 I/O36 1C12 (io), 55 I/O37 1C11 (io), 56 I/O38 1C8 (io), 57 I/O39 1C7 (io), 58 I/O40 1C4 (io), 59 I/O41 1C3 (io), 60 I/O42 1C2 (io), 61 I2/CLK2 (in), 62 VCC (power), 63 GND (power), 64 I3/CLK3 (in), 65 I/O43 0C2 (io), 66 I/O44 0C3 (io), 67 I/O45 0C4 (io), 68 I/O46 0C7 (io), 69 I/O47 0C8 (io), 70 I/O48 0C11 (io), 71 I/O49 0C12 (io), 72 I/O50 0C13 (io), 73 I/O51 0D14 (io), 74 TDO (out), 75 GND (power), 76 GND (power), 77 I/O52 0D13 (io), 78 I/O53 0D12 (io), 79 I/O54 0D11 (io), 80 I/O55 0D8 (io), 81 I/O56 0D7 (io), 82 I/O57 0D4 (io), 83 I/O58 0D3 (io), 84 I/O59 0D2 (io), 85 NC, 86 VCC (power), 87 GND (power), 88 GND (power), 89 VCC (power), 90 I/O60 0A2 (io), 91 I/O61 0A3 (io), 92 I/O62 0A4 (io), 93 I/O63 0A7 (io), 94 I/O64 0A8 (io), 95 I/O65 0A11 (io), 96 I/O66 0A12 (io), 97 I/O67 0A13 (io), 98 NC, 99 GND (power), 100 GND (power)

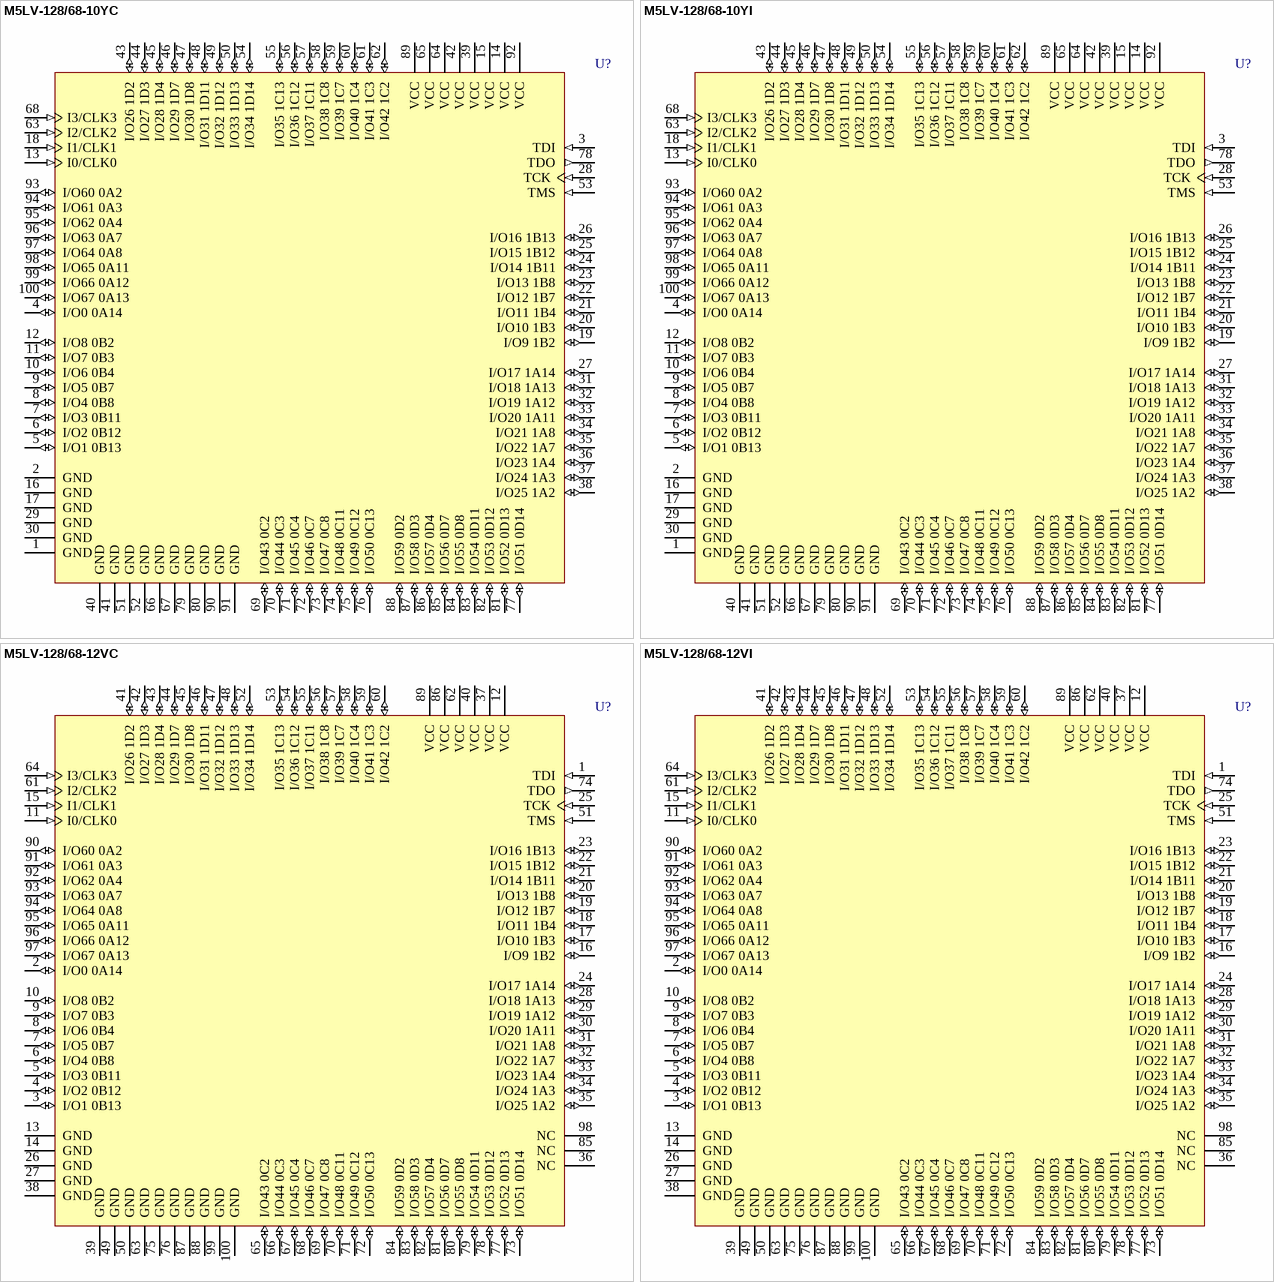
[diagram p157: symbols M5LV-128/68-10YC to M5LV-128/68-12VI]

## M5LV-128/68-10YC
designator U?
High-Density and High-I/O Complex PLD
footprint PQFP100_N (QFP, 100-Leads, Body 20x14mm, Pitch 0.65mm, IPC Medium Density)
footprint PQFP100_L (QFP, 100-Leads, Body 20x14mm, Pitch 0.65mm, IPC High Density)
footprint PQFP100_M (QFP, 100-Leads, Body 20x14mm, Pitch 0.65mm, IPC Low Density)
3D model PQFP-100 (100-Pin Quad Flat Pack Rectangular 0.65 mm Pitch)
pins: 1 GND (power), 2 GND (power), 3 TDI (in), 4 I/O0 0A14 (io), 5 I/O1 0B13 (io), 6 I/O2 0B12 (io), 7 I/O3 0B11 (io), 8 I/O4 0B8 (io), 9 I/O5 0B7 (io), 10 I/O6 0B4 (io), 11 I/O7 0B3 (io), 12 I/O8 0B2 (io), 13 I0/CLK0 (in), 14 VCC (power), 15 VCC (power), 16 GND (power), 17 GND (power), 18 I1/CLK1 (in), 19 I/O9 1B2 (io), 20 I/O10 1B3 (io), 21 I/O11 1B4 (io), 22 I/O12 1B7 (io), 23 I/O13 1B8 (io), 24 I/O14 1B11 (io), 25 I/O15 1B12 (io), 26 I/O16 1B13 (io), 27 I/O17 1A14 (io), 28 TCK (in), 29 GND (power), 30 GND (power), 31 I/O18 1A13 (io), 32 I/O19 1A12 (io), 33 I/O20 1A11 (io), 34 I/O21 1A8 (io), 35 I/O22 1A7 (io), 36 I/O23 1A4 (io), 37 I/O24 1A3 (io), 38 I/O25 1A2 (io), 39 VCC (power), 40 GND (power), 41 GND (power), 42 VCC (power), 43 I/O26 1D2 (io), 44 I/O27 1D3 (io), 45 I/O28 1D4 (io), 46 I/O29 1D7 (io), 47 I/O30 1D8 (io), 48 I/O31 1D11 (io), 49 I/O32 1D12 (io), 50 I/O33 1D13 (io), 51 GND (power), 52 GND (power), 53 TMS (in), 54 I/O34 1D14 (io), 55 I/O35 1C13 (io), 56 I/O36 1C12 (io), 57 I/O37 1C11 (io), 58 I/O38 1C8 (io), 59 I/O39 1C7 (io), 60 I/O40 1C4 (io), 61 I/O41 1C3 (io), 62 I/O42 1C2 (io), 63 I2/CLK2 (in), 64 VCC (power), 65 VCC (power), 66 GND (power), 67 GND (power), 68 I3/CLK3 (in), 69 I/O43 0C2 (io), 70 I/O44 0C3 (io), 71 I/O45 0C4 (io), 72 I/O46 0C7 (io), 73 I/O47 0C8 (io), 74 I/O48 0C11 (io), 75 I/O49 0C12 (io), 76 I/O50 0C13 (io), 77 I/O51 0D14 (io), 78 TDO (out), 79 GND (power), 80 GND (power), 81 I/O52 0D13 (io), 82 I/O53 0D12 (io), 83 I/O54 0D11 (io), 84 I/O55 0D8 (io), 85 I/O56 0D7 (io), 86 I/O57 0D4 (io), 87 I/O58 0D3 (io), 88 I/O59 0D2 (io), 89 VCC (power), 90 GND (power), 91 GND (power), 92 VCC (power), 93 I/O60 0A2 (io), 94 I/O61 0A3 (io), 95 I/O62 0A4 (io), 96 I/O63 0A7 (io), 97 I/O64 0A8 (io), 98 I/O65 0A11 (io), 99 I/O66 0A12 (io), 100 I/O67 0A13 (io)

## M5LV-128/68-10YI
designator U?
High-Density and High-I/O Complex PLD
footprint PQFP100_N (QFP, 100-Leads, Body 20x14mm, Pitch 0.65mm, IPC Medium Density)
footprint PQFP100_L (QFP, 100-Leads, Body 20x14mm, Pitch 0.65mm, IPC High Density)
footprint PQFP100_M (QFP, 100-Leads, Body 20x14mm, Pitch 0.65mm, IPC Low Density)
3D model PQFP-100 (100-Pin Quad Flat Pack Rectangular 0.65 mm Pitch)
pins: 1 GND (power), 2 GND (power), 3 TDI (in), 4 I/O0 0A14 (io), 5 I/O1 0B13 (io), 6 I/O2 0B12 (io), 7 I/O3 0B11 (io), 8 I/O4 0B8 (io), 9 I/O5 0B7 (io), 10 I/O6 0B4 (io), 11 I/O7 0B3 (io), 12 I/O8 0B2 (io), 13 I0/CLK0 (in), 14 VCC (power), 15 VCC (power), 16 GND (power), 17 GND (power), 18 I1/CLK1 (in), 19 I/O9 1B2 (io), 20 I/O10 1B3 (io), 21 I/O11 1B4 (io), 22 I/O12 1B7 (io), 23 I/O13 1B8 (io), 24 I/O14 1B11 (io), 25 I/O15 1B12 (io), 26 I/O16 1B13 (io), 27 I/O17 1A14 (io), 28 TCK (in), 29 GND (power), 30 GND (power), 31 I/O18 1A13 (io), 32 I/O19 1A12 (io), 33 I/O20 1A11 (io), 34 I/O21 1A8 (io), 35 I/O22 1A7 (io), 36 I/O23 1A4 (io), 37 I/O24 1A3 (io), 38 I/O25 1A2 (io), 39 VCC (power), 40 GND (power), 41 GND (power), 42 VCC (power), 43 I/O26 1D2 (io), 44 I/O27 1D3 (io), 45 I/O28 1D4 (io), 46 I/O29 1D7 (io), 47 I/O30 1D8 (io), 48 I/O31 1D11 (io), 49 I/O32 1D12 (io), 50 I/O33 1D13 (io), 51 GND (power), 52 GND (power), 53 TMS (in), 54 I/O34 1D14 (io), 55 I/O35 1C13 (io), 56 I/O36 1C12 (io), 57 I/O37 1C11 (io), 58 I/O38 1C8 (io), 59 I/O39 1C7 (io), 60 I/O40 1C4 (io), 61 I/O41 1C3 (io), 62 I/O42 1C2 (io), 63 I2/CLK2 (in), 64 VCC (power), 65 VCC (power), 66 GND (power), 67 GND (power), 68 I3/CLK3 (in), 69 I/O43 0C2 (io), 70 I/O44 0C3 (io), 71 I/O45 0C4 (io), 72 I/O46 0C7 (io), 73 I/O47 0C8 (io), 74 I/O48 0C11 (io), 75 I/O49 0C12 (io), 76 I/O50 0C13 (io), 77 I/O51 0D14 (io), 78 TDO (out), 79 GND (power), 80 GND (power), 81 I/O52 0D13 (io), 82 I/O53 0D12 (io), 83 I/O54 0D11 (io), 84 I/O55 0D8 (io), 85 I/O56 0D7 (io), 86 I/O57 0D4 (io), 87 I/O58 0D3 (io), 88 I/O59 0D2 (io), 89 VCC (power), 90 GND (power), 91 GND (power), 92 VCC (power), 93 I/O60 0A2 (io), 94 I/O61 0A3 (io), 95 I/O62 0A4 (io), 96 I/O63 0A7 (io), 97 I/O64 0A8 (io), 98 I/O65 0A11 (io), 99 I/O66 0A12 (io), 100 I/O67 0A13 (io)

## M5LV-128/68-12VC
designator U?
High-Density and High-I/O Complex PLD
footprint TQFP100_N (Thin QFP, 100-Leads, Body 14x14mm, Pitch 0.5mm, IPC Medium Density)
footprint TQFP100_L (Thin QFP, 100-Leads, Body 14x14mm, Pitch 0.5mm, IPC High Density)
footprint TQFP100_M (Thin QFP, 100-Leads, Body 14x14mm, Pitch 0.5mm, IPC Low Density)
3D model M5LV-TQFP100 (100-Pin Thin Quad Flat Pack (TQFP100))
pins: 1 TDI (in), 2 I/O0 0A14 (io), 3 I/O1 0B13 (io), 4 I/O2 0B12 (io), 5 I/O3 0B11 (io), 6 I/O4 0B8 (io), 7 I/O5 0B7 (io), 8 I/O6 0B4 (io), 9 I/O7 0B3 (io), 10 I/O8 0B2 (io), 11 I0/CLK0 (in), 12 VCC (power), 13 GND (power), 14 GND (power), 15 I1/CLK1 (in), 16 I/O9 1B2 (io), 17 I/O10 1B3 (io), 18 I/O11 1B4 (io), 19 I/O12 1B7 (io), 20 I/O13 1B8 (io), 21 I/O14 1B11 (io), 22 I/O15 1B12 (io), 23 I/O16 1B13 (io), 24 I/O17 1A14 (io), 25 TCK (in), 26 GND (power), 27 GND (power), 28 I/O18 1A13 (io), 29 I/O19 1A12 (io), 30 I/O20 1A11 (io), 31 I/O21 1A8 (io), 32 I/O22 1A7 (io), 33 I/O23 1A4 (io), 34 I/O24 1A3 (io), 35 I/O25 1A2 (io), 36 NC, 37 VCC (power), 38 GND (power), 39 GND (power), 40 VCC (power), 41 I/O26 1D2 (io), 42 I/O27 1D3 (io), 43 I/O28 1D4 (io), 44 I/O29 1D7 (io), 45 I/O30 1D8 (io), 46 I/O31 1D11 (io), 47 I/O32 1D12 (io), 48 I/O33 1D13 (io), 49 GND (power), 50 GND (power), 51 TMS (in), 52 I/O34 1D14 (io), 53 I/O35 1C13 (io), 54 I/O36 1C12 (io), 55 I/O37 1C11 (io), 56 I/O38 1C8 (io), 57 I/O39 1C7 (io), 58 I/O40 1C4 (io), 59 I/O41 1C3 (io), 60 I/O42 1C2 (io), 61 I2/CLK2 (in), 62 VCC (power), 63 GND (power), 64 I3/CLK3 (in), 65 I/O43 0C2 (io), 66 I/O44 0C3 (io), 67 I/O45 0C4 (io), 68 I/O46 0C7 (io), 69 I/O47 0C8 (io), 70 I/O48 0C11 (io), 71 I/O49 0C12 (io), 72 I/O50 0C13 (io), 73 I/O51 0D14 (io), 74 TDO (out), 75 GND (power), 76 GND (power), 77 I/O52 0D13 (io), 78 I/O53 0D12 (io), 79 I/O54 0D11 (io), 80 I/O55 0D8 (io), 81 I/O56 0D7 (io), 82 I/O57 0D4 (io), 83 I/O58 0D3 (io), 84 I/O59 0D2 (io), 85 NC, 86 VCC (power), 87 GND (power), 88 GND (power), 89 VCC (power), 90 I/O60 0A2 (io), 91 I/O61 0A3 (io), 92 I/O62 0A4 (io), 93 I/O63 0A7 (io), 94 I/O64 0A8 (io), 95 I/O65 0A11 (io), 96 I/O66 0A12 (io), 97 I/O67 0A13 (io), 98 NC, 99 GND (power), 100 GND (power)

## M5LV-128/68-12VI
designator U?
High-Density and High-I/O Complex PLD
footprint TQFP100_N (Thin QFP, 100-Leads, Body 14x14mm, Pitch 0.5mm, IPC Medium Density)
footprint TQFP100_L (Thin QFP, 100-Leads, Body 14x14mm, Pitch 0.5mm, IPC High Density)
footprint TQFP100_M (Thin QFP, 100-Leads, Body 14x14mm, Pitch 0.5mm, IPC Low Density)
3D model M5LV-TQFP100 (100-Pin Thin Quad Flat Pack (TQFP100))
pins: 1 TDI (in), 2 I/O0 0A14 (io), 3 I/O1 0B13 (io), 4 I/O2 0B12 (io), 5 I/O3 0B11 (io), 6 I/O4 0B8 (io), 7 I/O5 0B7 (io), 8 I/O6 0B4 (io), 9 I/O7 0B3 (io), 10 I/O8 0B2 (io), 11 I0/CLK0 (in), 12 VCC (power), 13 GND (power), 14 GND (power), 15 I1/CLK1 (in), 16 I/O9 1B2 (io), 17 I/O10 1B3 (io), 18 I/O11 1B4 (io), 19 I/O12 1B7 (io), 20 I/O13 1B8 (io), 21 I/O14 1B11 (io), 22 I/O15 1B12 (io), 23 I/O16 1B13 (io), 24 I/O17 1A14 (io), 25 TCK (in), 26 GND (power), 27 GND (power), 28 I/O18 1A13 (io), 29 I/O19 1A12 (io), 30 I/O20 1A11 (io), 31 I/O21 1A8 (io), 32 I/O22 1A7 (io), 33 I/O23 1A4 (io), 34 I/O24 1A3 (io), 35 I/O25 1A2 (io), 36 NC, 37 VCC (power), 38 GND (power), 39 GND (power), 40 VCC (power), 41 I/O26 1D2 (io), 42 I/O27 1D3 (io), 43 I/O28 1D4 (io), 44 I/O29 1D7 (io), 45 I/O30 1D8 (io), 46 I/O31 1D11 (io), 47 I/O32 1D12 (io), 48 I/O33 1D13 (io), 49 GND (power), 50 GND (power), 51 TMS (in), 52 I/O34 1D14 (io), 53 I/O35 1C13 (io), 54 I/O36 1C12 (io), 55 I/O37 1C11 (io), 56 I/O38 1C8 (io), 57 I/O39 1C7 (io), 58 I/O40 1C4 (io), 59 I/O41 1C3 (io), 60 I/O42 1C2 (io), 61 I2/CLK2 (in), 62 VCC (power), 63 GND (power), 64 I3/CLK3 (in), 65 I/O43 0C2 (io), 66 I/O44 0C3 (io), 67 I/O45 0C4 (io), 68 I/O46 0C7 (io), 69 I/O47 0C8 (io), 70 I/O48 0C11 (io), 71 I/O49 0C12 (io), 72 I/O50 0C13 (io), 73 I/O51 0D14 (io), 74 TDO (out), 75 GND (power), 76 GND (power), 77 I/O52 0D13 (io), 78 I/O53 0D12 (io), 79 I/O54 0D11 (io), 80 I/O55 0D8 (io), 81 I/O56 0D7 (io), 82 I/O57 0D4 (io), 83 I/O58 0D3 (io), 84 I/O59 0D2 (io), 85 NC, 86 VCC (power), 87 GND (power), 88 GND (power), 89 VCC (power), 90 I/O60 0A2 (io), 91 I/O61 0A3 (io), 92 I/O62 0A4 (io), 93 I/O63 0A7 (io), 94 I/O64 0A8 (io), 95 I/O65 0A11 (io), 96 I/O66 0A12 (io), 97 I/O67 0A13 (io), 98 NC, 99 GND (power), 100 GND (power)

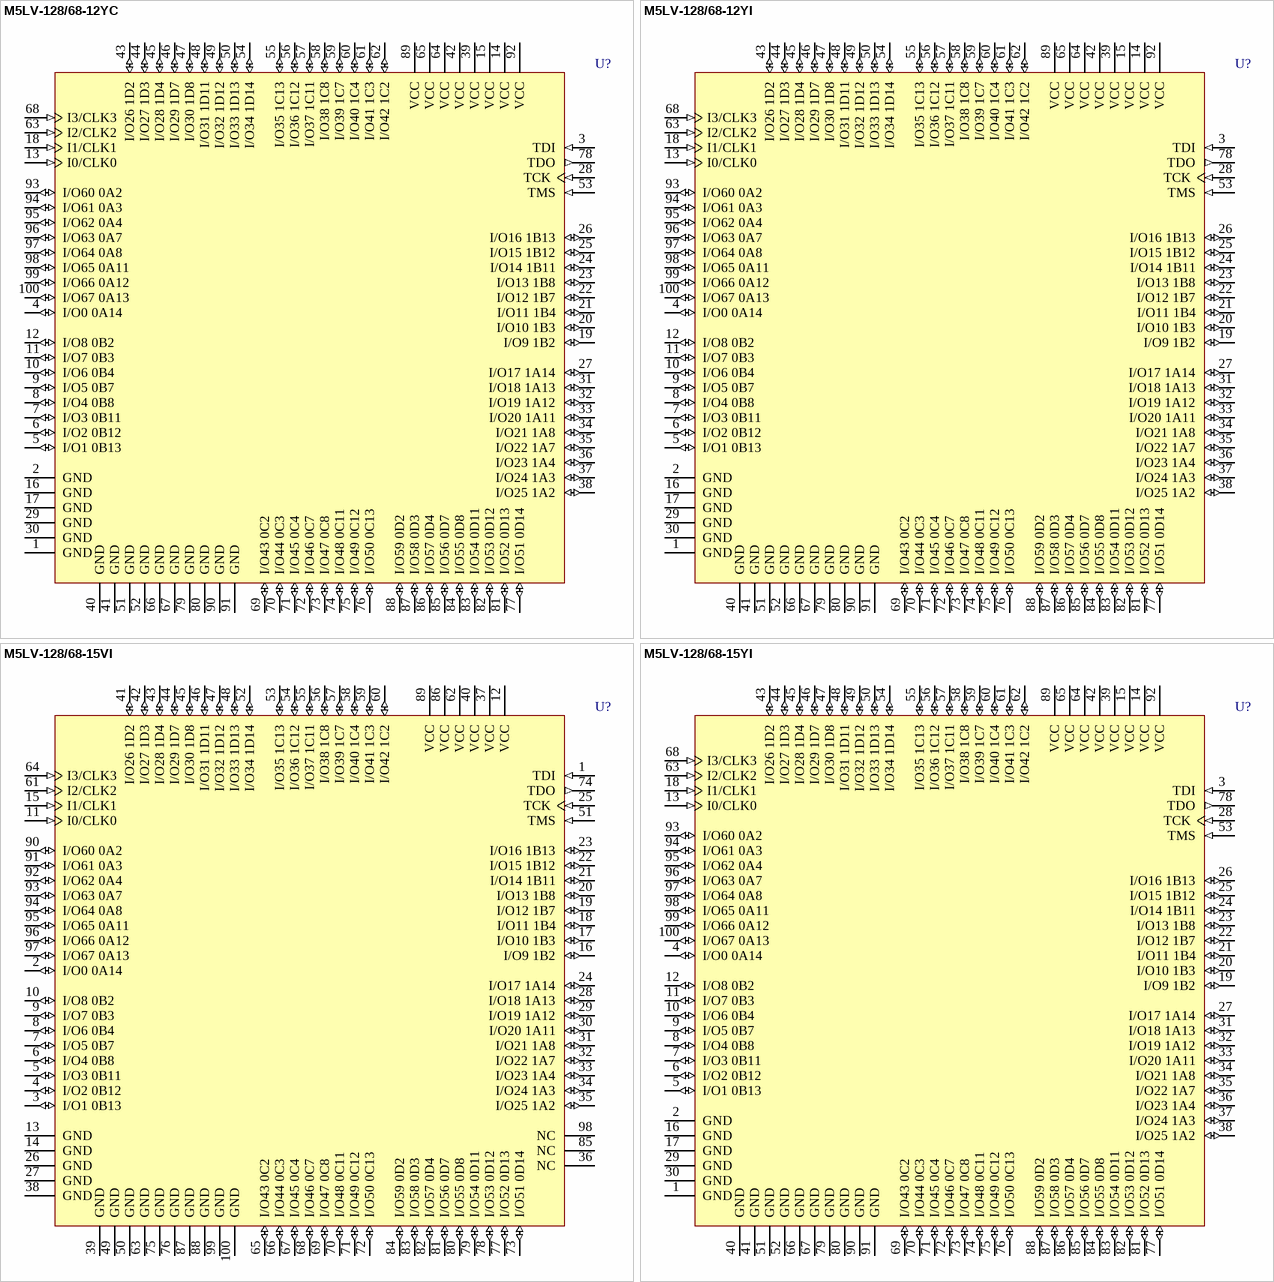
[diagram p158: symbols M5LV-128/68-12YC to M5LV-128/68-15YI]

## M5LV-128/68-12YC
designator U?
High-Density and High-I/O Complex PLD
footprint PQFP100_N (QFP, 100-Leads, Body 20x14mm, Pitch 0.65mm, IPC Medium Density)
footprint PQFP100_L (QFP, 100-Leads, Body 20x14mm, Pitch 0.65mm, IPC High Density)
footprint PQFP100_M (QFP, 100-Leads, Body 20x14mm, Pitch 0.65mm, IPC Low Density)
3D model PQFP-100 (100-Pin Quad Flat Pack Rectangular 0.65 mm Pitch)
pins: 1 GND (power), 2 GND (power), 3 TDI (in), 4 I/O0 0A14 (io), 5 I/O1 0B13 (io), 6 I/O2 0B12 (io), 7 I/O3 0B11 (io), 8 I/O4 0B8 (io), 9 I/O5 0B7 (io), 10 I/O6 0B4 (io), 11 I/O7 0B3 (io), 12 I/O8 0B2 (io), 13 I0/CLK0 (in), 14 VCC (power), 15 VCC (power), 16 GND (power), 17 GND (power), 18 I1/CLK1 (in), 19 I/O9 1B2 (io), 20 I/O10 1B3 (io), 21 I/O11 1B4 (io), 22 I/O12 1B7 (io), 23 I/O13 1B8 (io), 24 I/O14 1B11 (io), 25 I/O15 1B12 (io), 26 I/O16 1B13 (io), 27 I/O17 1A14 (io), 28 TCK (in), 29 GND (power), 30 GND (power), 31 I/O18 1A13 (io), 32 I/O19 1A12 (io), 33 I/O20 1A11 (io), 34 I/O21 1A8 (io), 35 I/O22 1A7 (io), 36 I/O23 1A4 (io), 37 I/O24 1A3 (io), 38 I/O25 1A2 (io), 39 VCC (power), 40 GND (power), 41 GND (power), 42 VCC (power), 43 I/O26 1D2 (io), 44 I/O27 1D3 (io), 45 I/O28 1D4 (io), 46 I/O29 1D7 (io), 47 I/O30 1D8 (io), 48 I/O31 1D11 (io), 49 I/O32 1D12 (io), 50 I/O33 1D13 (io), 51 GND (power), 52 GND (power), 53 TMS (in), 54 I/O34 1D14 (io), 55 I/O35 1C13 (io), 56 I/O36 1C12 (io), 57 I/O37 1C11 (io), 58 I/O38 1C8 (io), 59 I/O39 1C7 (io), 60 I/O40 1C4 (io), 61 I/O41 1C3 (io), 62 I/O42 1C2 (io), 63 I2/CLK2 (in), 64 VCC (power), 65 VCC (power), 66 GND (power), 67 GND (power), 68 I3/CLK3 (in), 69 I/O43 0C2 (io), 70 I/O44 0C3 (io), 71 I/O45 0C4 (io), 72 I/O46 0C7 (io), 73 I/O47 0C8 (io), 74 I/O48 0C11 (io), 75 I/O49 0C12 (io), 76 I/O50 0C13 (io), 77 I/O51 0D14 (io), 78 TDO (out), 79 GND (power), 80 GND (power), 81 I/O52 0D13 (io), 82 I/O53 0D12 (io), 83 I/O54 0D11 (io), 84 I/O55 0D8 (io), 85 I/O56 0D7 (io), 86 I/O57 0D4 (io), 87 I/O58 0D3 (io), 88 I/O59 0D2 (io), 89 VCC (power), 90 GND (power), 91 GND (power), 92 VCC (power), 93 I/O60 0A2 (io), 94 I/O61 0A3 (io), 95 I/O62 0A4 (io), 96 I/O63 0A7 (io), 97 I/O64 0A8 (io), 98 I/O65 0A11 (io), 99 I/O66 0A12 (io), 100 I/O67 0A13 (io)

## M5LV-128/68-12YI
designator U?
High-Density and High-I/O Complex PLD
footprint PQFP100_N (QFP, 100-Leads, Body 20x14mm, Pitch 0.65mm, IPC Medium Density)
footprint PQFP100_L (QFP, 100-Leads, Body 20x14mm, Pitch 0.65mm, IPC High Density)
footprint PQFP100_M (QFP, 100-Leads, Body 20x14mm, Pitch 0.65mm, IPC Low Density)
3D model PQFP-100 (100-Pin Quad Flat Pack Rectangular 0.65 mm Pitch)
pins: 1 GND (power), 2 GND (power), 3 TDI (in), 4 I/O0 0A14 (io), 5 I/O1 0B13 (io), 6 I/O2 0B12 (io), 7 I/O3 0B11 (io), 8 I/O4 0B8 (io), 9 I/O5 0B7 (io), 10 I/O6 0B4 (io), 11 I/O7 0B3 (io), 12 I/O8 0B2 (io), 13 I0/CLK0 (in), 14 VCC (power), 15 VCC (power), 16 GND (power), 17 GND (power), 18 I1/CLK1 (in), 19 I/O9 1B2 (io), 20 I/O10 1B3 (io), 21 I/O11 1B4 (io), 22 I/O12 1B7 (io), 23 I/O13 1B8 (io), 24 I/O14 1B11 (io), 25 I/O15 1B12 (io), 26 I/O16 1B13 (io), 27 I/O17 1A14 (io), 28 TCK (in), 29 GND (power), 30 GND (power), 31 I/O18 1A13 (io), 32 I/O19 1A12 (io), 33 I/O20 1A11 (io), 34 I/O21 1A8 (io), 35 I/O22 1A7 (io), 36 I/O23 1A4 (io), 37 I/O24 1A3 (io), 38 I/O25 1A2 (io), 39 VCC (power), 40 GND (power), 41 GND (power), 42 VCC (power), 43 I/O26 1D2 (io), 44 I/O27 1D3 (io), 45 I/O28 1D4 (io), 46 I/O29 1D7 (io), 47 I/O30 1D8 (io), 48 I/O31 1D11 (io), 49 I/O32 1D12 (io), 50 I/O33 1D13 (io), 51 GND (power), 52 GND (power), 53 TMS (in), 54 I/O34 1D14 (io), 55 I/O35 1C13 (io), 56 I/O36 1C12 (io), 57 I/O37 1C11 (io), 58 I/O38 1C8 (io), 59 I/O39 1C7 (io), 60 I/O40 1C4 (io), 61 I/O41 1C3 (io), 62 I/O42 1C2 (io), 63 I2/CLK2 (in), 64 VCC (power), 65 VCC (power), 66 GND (power), 67 GND (power), 68 I3/CLK3 (in), 69 I/O43 0C2 (io), 70 I/O44 0C3 (io), 71 I/O45 0C4 (io), 72 I/O46 0C7 (io), 73 I/O47 0C8 (io), 74 I/O48 0C11 (io), 75 I/O49 0C12 (io), 76 I/O50 0C13 (io), 77 I/O51 0D14 (io), 78 TDO (out), 79 GND (power), 80 GND (power), 81 I/O52 0D13 (io), 82 I/O53 0D12 (io), 83 I/O54 0D11 (io), 84 I/O55 0D8 (io), 85 I/O56 0D7 (io), 86 I/O57 0D4 (io), 87 I/O58 0D3 (io), 88 I/O59 0D2 (io), 89 VCC (power), 90 GND (power), 91 GND (power), 92 VCC (power), 93 I/O60 0A2 (io), 94 I/O61 0A3 (io), 95 I/O62 0A4 (io), 96 I/O63 0A7 (io), 97 I/O64 0A8 (io), 98 I/O65 0A11 (io), 99 I/O66 0A12 (io), 100 I/O67 0A13 (io)

## M5LV-128/68-15VI
designator U?
High-Density and High-I/O Complex PLD
footprint TQFP100_N (Thin QFP, 100-Leads, Body 14x14mm, Pitch 0.5mm, IPC Medium Density)
footprint TQFP100_L (Thin QFP, 100-Leads, Body 14x14mm, Pitch 0.5mm, IPC High Density)
footprint TQFP100_M (Thin QFP, 100-Leads, Body 14x14mm, Pitch 0.5mm, IPC Low Density)
3D model M5LV-TQFP100 (100-Pin Thin Quad Flat Pack (TQFP100))
pins: 1 TDI (in), 2 I/O0 0A14 (io), 3 I/O1 0B13 (io), 4 I/O2 0B12 (io), 5 I/O3 0B11 (io), 6 I/O4 0B8 (io), 7 I/O5 0B7 (io), 8 I/O6 0B4 (io), 9 I/O7 0B3 (io), 10 I/O8 0B2 (io), 11 I0/CLK0 (in), 12 VCC (power), 13 GND (power), 14 GND (power), 15 I1/CLK1 (in), 16 I/O9 1B2 (io), 17 I/O10 1B3 (io), 18 I/O11 1B4 (io), 19 I/O12 1B7 (io), 20 I/O13 1B8 (io), 21 I/O14 1B11 (io), 22 I/O15 1B12 (io), 23 I/O16 1B13 (io), 24 I/O17 1A14 (io), 25 TCK (in), 26 GND (power), 27 GND (power), 28 I/O18 1A13 (io), 29 I/O19 1A12 (io), 30 I/O20 1A11 (io), 31 I/O21 1A8 (io), 32 I/O22 1A7 (io), 33 I/O23 1A4 (io), 34 I/O24 1A3 (io), 35 I/O25 1A2 (io), 36 NC, 37 VCC (power), 38 GND (power), 39 GND (power), 40 VCC (power), 41 I/O26 1D2 (io), 42 I/O27 1D3 (io), 43 I/O28 1D4 (io), 44 I/O29 1D7 (io), 45 I/O30 1D8 (io), 46 I/O31 1D11 (io), 47 I/O32 1D12 (io), 48 I/O33 1D13 (io), 49 GND (power), 50 GND (power), 51 TMS (in), 52 I/O34 1D14 (io), 53 I/O35 1C13 (io), 54 I/O36 1C12 (io), 55 I/O37 1C11 (io), 56 I/O38 1C8 (io), 57 I/O39 1C7 (io), 58 I/O40 1C4 (io), 59 I/O41 1C3 (io), 60 I/O42 1C2 (io), 61 I2/CLK2 (in), 62 VCC (power), 63 GND (power), 64 I3/CLK3 (in), 65 I/O43 0C2 (io), 66 I/O44 0C3 (io), 67 I/O45 0C4 (io), 68 I/O46 0C7 (io), 69 I/O47 0C8 (io), 70 I/O48 0C11 (io), 71 I/O49 0C12 (io), 72 I/O50 0C13 (io), 73 I/O51 0D14 (io), 74 TDO (out), 75 GND (power), 76 GND (power), 77 I/O52 0D13 (io), 78 I/O53 0D12 (io), 79 I/O54 0D11 (io), 80 I/O55 0D8 (io), 81 I/O56 0D7 (io), 82 I/O57 0D4 (io), 83 I/O58 0D3 (io), 84 I/O59 0D2 (io), 85 NC, 86 VCC (power), 87 GND (power), 88 GND (power), 89 VCC (power), 90 I/O60 0A2 (io), 91 I/O61 0A3 (io), 92 I/O62 0A4 (io), 93 I/O63 0A7 (io), 94 I/O64 0A8 (io), 95 I/O65 0A11 (io), 96 I/O66 0A12 (io), 97 I/O67 0A13 (io), 98 NC, 99 GND (power), 100 GND (power)

## M5LV-128/68-15YI
designator U?
High-Density and High-I/O Complex PLD
footprint PQFP100_N (QFP, 100-Leads, Body 20x14mm, Pitch 0.65mm, IPC Medium Density)
footprint PQFP100_L (QFP, 100-Leads, Body 20x14mm, Pitch 0.65mm, IPC High Density)
footprint PQFP100_M (QFP, 100-Leads, Body 20x14mm, Pitch 0.65mm, IPC Low Density)
3D model PQFP-100 (100-Pin Quad Flat Pack Rectangular 0.65 mm Pitch)
pins: 1 GND (power), 2 GND (power), 3 TDI (in), 4 I/O0 0A14 (io), 5 I/O1 0B13 (io), 6 I/O2 0B12 (io), 7 I/O3 0B11 (io), 8 I/O4 0B8 (io), 9 I/O5 0B7 (io), 10 I/O6 0B4 (io), 11 I/O7 0B3 (io), 12 I/O8 0B2 (io), 13 I0/CLK0 (in), 14 VCC (power), 15 VCC (power), 16 GND (power), 17 GND (power), 18 I1/CLK1 (in), 19 I/O9 1B2 (io), 20 I/O10 1B3 (io), 21 I/O11 1B4 (io), 22 I/O12 1B7 (io), 23 I/O13 1B8 (io), 24 I/O14 1B11 (io), 25 I/O15 1B12 (io), 26 I/O16 1B13 (io), 27 I/O17 1A14 (io), 28 TCK (in), 29 GND (power), 30 GND (power), 31 I/O18 1A13 (io), 32 I/O19 1A12 (io), 33 I/O20 1A11 (io), 34 I/O21 1A8 (io), 35 I/O22 1A7 (io), 36 I/O23 1A4 (io), 37 I/O24 1A3 (io), 38 I/O25 1A2 (io), 39 VCC (power), 40 GND (power), 41 GND (power), 42 VCC (power), 43 I/O26 1D2 (io), 44 I/O27 1D3 (io), 45 I/O28 1D4 (io), 46 I/O29 1D7 (io), 47 I/O30 1D8 (io), 48 I/O31 1D11 (io), 49 I/O32 1D12 (io), 50 I/O33 1D13 (io), 51 GND (power), 52 GND (power), 53 TMS (in), 54 I/O34 1D14 (io), 55 I/O35 1C13 (io), 56 I/O36 1C12 (io), 57 I/O37 1C11 (io), 58 I/O38 1C8 (io), 59 I/O39 1C7 (io), 60 I/O40 1C4 (io), 61 I/O41 1C3 (io), 62 I/O42 1C2 (io), 63 I2/CLK2 (in), 64 VCC (power), 65 VCC (power), 66 GND (power), 67 GND (power), 68 I3/CLK3 (in), 69 I/O43 0C2 (io), 70 I/O44 0C3 (io), 71 I/O45 0C4 (io), 72 I/O46 0C7 (io), 73 I/O47 0C8 (io), 74 I/O48 0C11 (io), 75 I/O49 0C12 (io), 76 I/O50 0C13 (io), 77 I/O51 0D14 (io), 78 TDO (out), 79 GND (power), 80 GND (power), 81 I/O52 0D13 (io), 82 I/O53 0D12 (io), 83 I/O54 0D11 (io), 84 I/O55 0D8 (io), 85 I/O56 0D7 (io), 86 I/O57 0D4 (io), 87 I/O58 0D3 (io), 88 I/O59 0D2 (io), 89 VCC (power), 90 GND (power), 91 GND (power), 92 VCC (power), 93 I/O60 0A2 (io), 94 I/O61 0A3 (io), 95 I/O62 0A4 (io), 96 I/O63 0A7 (io), 97 I/O64 0A8 (io), 98 I/O65 0A11 (io), 99 I/O66 0A12 (io), 100 I/O67 0A13 (io)

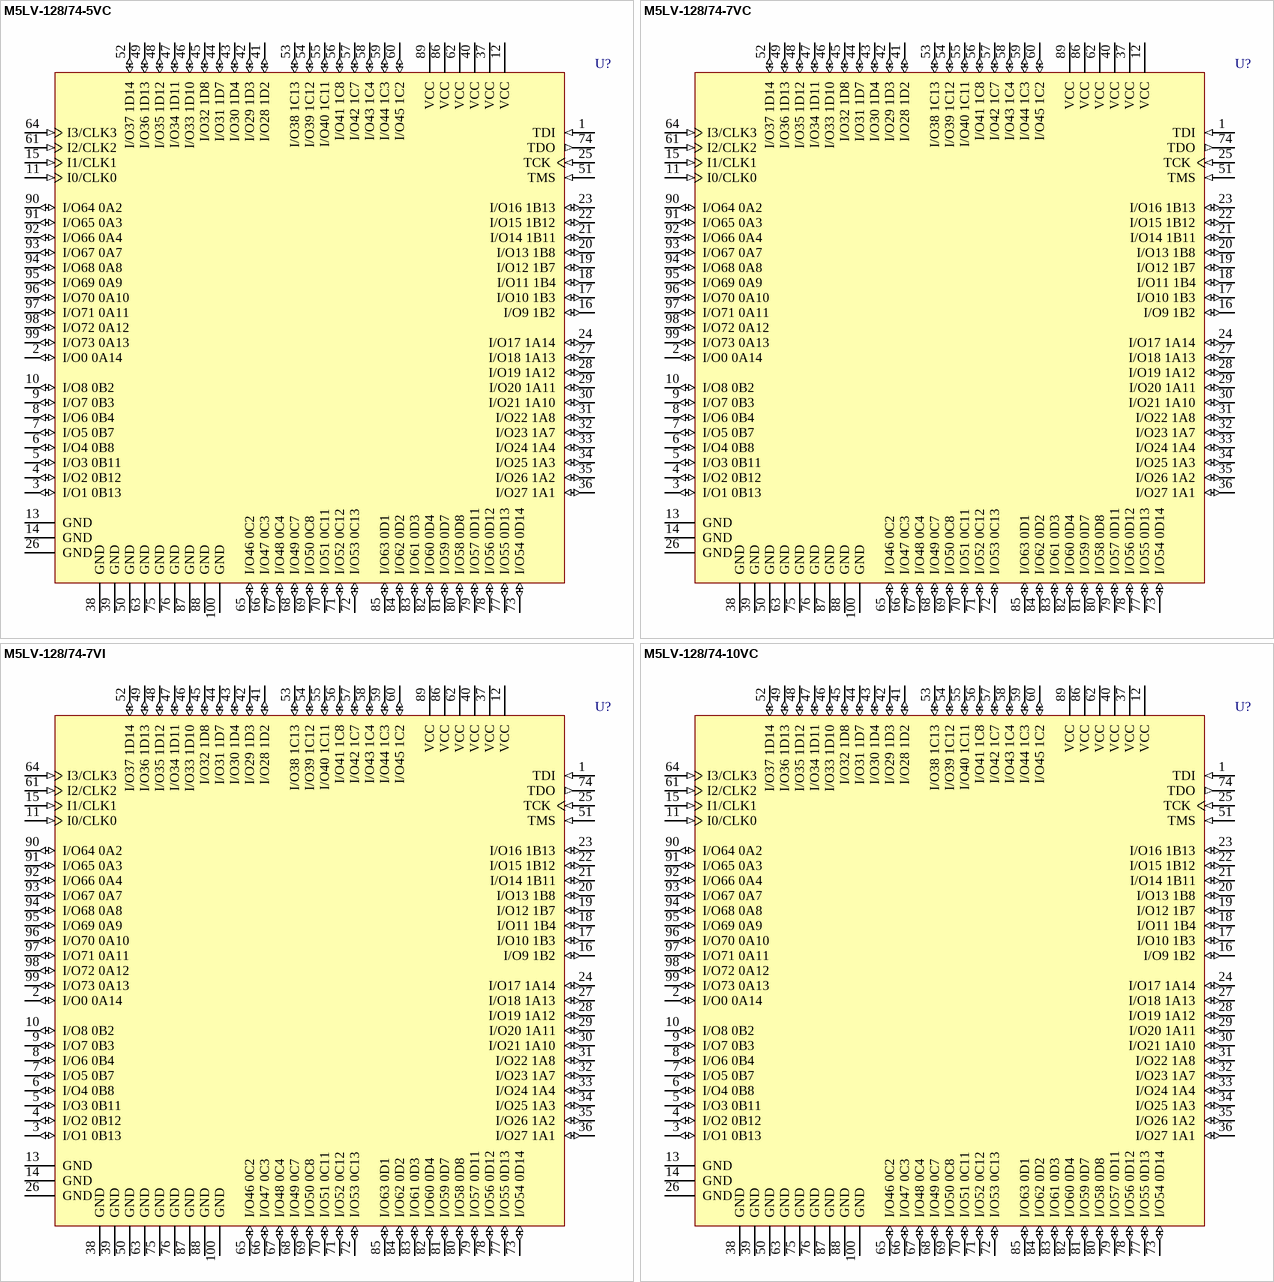
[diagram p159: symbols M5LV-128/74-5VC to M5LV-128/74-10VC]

## M5LV-128/74-5VC
designator U?
High-Density and High-I/O Complex PLD
footprint TQFP100_N (Thin QFP, 100-Leads, Body 14x14mm, Pitch 0.5mm, IPC Medium Density)
footprint TQFP100_L (Thin QFP, 100-Leads, Body 14x14mm, Pitch 0.5mm, IPC High Density)
footprint TQFP100_M (Thin QFP, 100-Leads, Body 14x14mm, Pitch 0.5mm, IPC Low Density)
3D model M5LV-TQFP100 (100-Pin Thin Quad Flat Pack (TQFP100))
pins: 1 TDI (in), 2 I/O0 0A14 (io), 3 I/O1 0B13 (io), 4 I/O2 0B12 (io), 5 I/O3 0B11 (io), 6 I/O4 0B8 (io), 7 I/O5 0B7 (io), 8 I/O6 0B4 (io), 9 I/O7 0B3 (io), 10 I/O8 0B2 (io), 11 I0/CLK0 (in), 12 VCC (power), 13 GND (power), 14 GND (power), 15 I1/CLK1 (in), 16 I/O9 1B2 (io), 17 I/O10 1B3 (io), 18 I/O11 1B4 (io), 19 I/O12 1B7 (io), 20 I/O13 1B8 (io), 21 I/O14 1B11 (io), 22 I/O15 1B12 (io), 23 I/O16 1B13 (io), 24 I/O17 1A14 (io), 25 TCK (in), 26 GND (power), 27 I/O18 1A13 (io), 28 I/O19 1A12 (io), 29 I/O20 1A11 (io), 30 I/O21 1A10 (io), 31 I/O22 1A8 (io), 32 I/O23 1A7 (io), 33 I/O24 1A4 (io), 34 I/O25 1A3 (io), 35 I/O26 1A2 (io), 36 I/O27 1A1 (io), 37 VCC (power), 38 GND (power), 39 GND (power), 40 VCC (power), 41 I/O28 1D2 (io), 42 I/O29 1D3 (io), 43 I/O30 1D4 (io), 44 I/O31 1D7 (io), 45 I/O32 1D8 (io), 46 I/O33 1D10 (io), 47 I/O34 1D11 (io), 48 I/O35 1D12 (io), 49 I/O36 1D13 (io), 50 GND (power), 51 TMS (in), 52 I/O37 1D14 (io), 53 I/O38 1C13 (io), 54 I/O39 1C12 (io), 55 I/O40 1C11 (io), 56 I/O41 1C8 (io), 57 I/O42 1C7 (io), 58 I/O43 1C4 (io), 59 I/O44 1C3 (io), 60 I/O45 1C2 (io), 61 I2/CLK2 (in), 62 VCC (power), 63 GND (power), 64 I3/CLK3 (in), 65 I/O46 0C2 (io), 66 I/O47 0C3 (io), 67 I/O48 0C4 (io), 68 I/O49 0C7 (io), 69 I/O50 0C8 (io), 70 I/O51 0C11 (io), 71 I/O52 0C12 (io), 72 I/O53 0C13 (io), 73 I/O54 0D14 (io), 74 TDO (out), 75 GND (power), 76 GND (power), 77 I/O55 0D13 (io), 78 I/O56 0D12 (io), 79 I/O57 0D11 (io), 80 I/O58 0D8 (io), 81 I/O59 0D7 (io), 82 I/O60 0D4 (io), 83 I/O61 0D3 (io), 84 I/O62 0D2 (io), 85 I/O63 0D1 (io), 86 VCC (power), 87 GND (power), 88 GND (power), 89 VCC (power), 90 I/O64 0A2 (io), 91 I/O65 0A3 (io), 92 I/O66 0A4 (io), 93 I/O67 0A7 (io), 94 I/O68 0A8 (io), 95 I/O69 0A9 (io), 96 I/O70 0A10 (io), 97 I/O71 0A11 (io), 98 I/O72 0A12 (io), 99 I/O73 0A13 (io), 100 GND (power)

## M5LV-128/74-7VC
designator U?
High-Density and High-I/O Complex PLD
footprint TQFP100_N (Thin QFP, 100-Leads, Body 14x14mm, Pitch 0.5mm, IPC Medium Density)
footprint TQFP100_L (Thin QFP, 100-Leads, Body 14x14mm, Pitch 0.5mm, IPC High Density)
footprint TQFP100_M (Thin QFP, 100-Leads, Body 14x14mm, Pitch 0.5mm, IPC Low Density)
3D model M5LV-TQFP100 (100-Pin Thin Quad Flat Pack (TQFP100))
pins: 1 TDI (in), 2 I/O0 0A14 (io), 3 I/O1 0B13 (io), 4 I/O2 0B12 (io), 5 I/O3 0B11 (io), 6 I/O4 0B8 (io), 7 I/O5 0B7 (io), 8 I/O6 0B4 (io), 9 I/O7 0B3 (io), 10 I/O8 0B2 (io), 11 I0/CLK0 (in), 12 VCC (power), 13 GND (power), 14 GND (power), 15 I1/CLK1 (in), 16 I/O9 1B2 (io), 17 I/O10 1B3 (io), 18 I/O11 1B4 (io), 19 I/O12 1B7 (io), 20 I/O13 1B8 (io), 21 I/O14 1B11 (io), 22 I/O15 1B12 (io), 23 I/O16 1B13 (io), 24 I/O17 1A14 (io), 25 TCK (in), 26 GND (power), 27 I/O18 1A13 (io), 28 I/O19 1A12 (io), 29 I/O20 1A11 (io), 30 I/O21 1A10 (io), 31 I/O22 1A8 (io), 32 I/O23 1A7 (io), 33 I/O24 1A4 (io), 34 I/O25 1A3 (io), 35 I/O26 1A2 (io), 36 I/O27 1A1 (io), 37 VCC (power), 38 GND (power), 39 GND (power), 40 VCC (power), 41 I/O28 1D2 (io), 42 I/O29 1D3 (io), 43 I/O30 1D4 (io), 44 I/O31 1D7 (io), 45 I/O32 1D8 (io), 46 I/O33 1D10 (io), 47 I/O34 1D11 (io), 48 I/O35 1D12 (io), 49 I/O36 1D13 (io), 50 GND (power), 51 TMS (in), 52 I/O37 1D14 (io), 53 I/O38 1C13 (io), 54 I/O39 1C12 (io), 55 I/O40 1C11 (io), 56 I/O41 1C8 (io), 57 I/O42 1C7 (io), 58 I/O43 1C4 (io), 59 I/O44 1C3 (io), 60 I/O45 1C2 (io), 61 I2/CLK2 (in), 62 VCC (power), 63 GND (power), 64 I3/CLK3 (in), 65 I/O46 0C2 (io), 66 I/O47 0C3 (io), 67 I/O48 0C4 (io), 68 I/O49 0C7 (io), 69 I/O50 0C8 (io), 70 I/O51 0C11 (io), 71 I/O52 0C12 (io), 72 I/O53 0C13 (io), 73 I/O54 0D14 (io), 74 TDO (out), 75 GND (power), 76 GND (power), 77 I/O55 0D13 (io), 78 I/O56 0D12 (io), 79 I/O57 0D11 (io), 80 I/O58 0D8 (io), 81 I/O59 0D7 (io), 82 I/O60 0D4 (io), 83 I/O61 0D3 (io), 84 I/O62 0D2 (io), 85 I/O63 0D1 (io), 86 VCC (power), 87 GND (power), 88 GND (power), 89 VCC (power), 90 I/O64 0A2 (io), 91 I/O65 0A3 (io), 92 I/O66 0A4 (io), 93 I/O67 0A7 (io), 94 I/O68 0A8 (io), 95 I/O69 0A9 (io), 96 I/O70 0A10 (io), 97 I/O71 0A11 (io), 98 I/O72 0A12 (io), 99 I/O73 0A13 (io), 100 GND (power)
